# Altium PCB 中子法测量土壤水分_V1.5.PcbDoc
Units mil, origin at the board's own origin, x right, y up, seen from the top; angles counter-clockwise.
Board outline 3543.31 x 2393.7 mil, 4 copper layers (Top Layer, Signal Layer1, Signal Layer2, Bottom Layer), stack 30.634 mil thick; 164 components, 104 nets, 491 pads, 224 vias.
Unrouted connection lines stored in the file: 1.
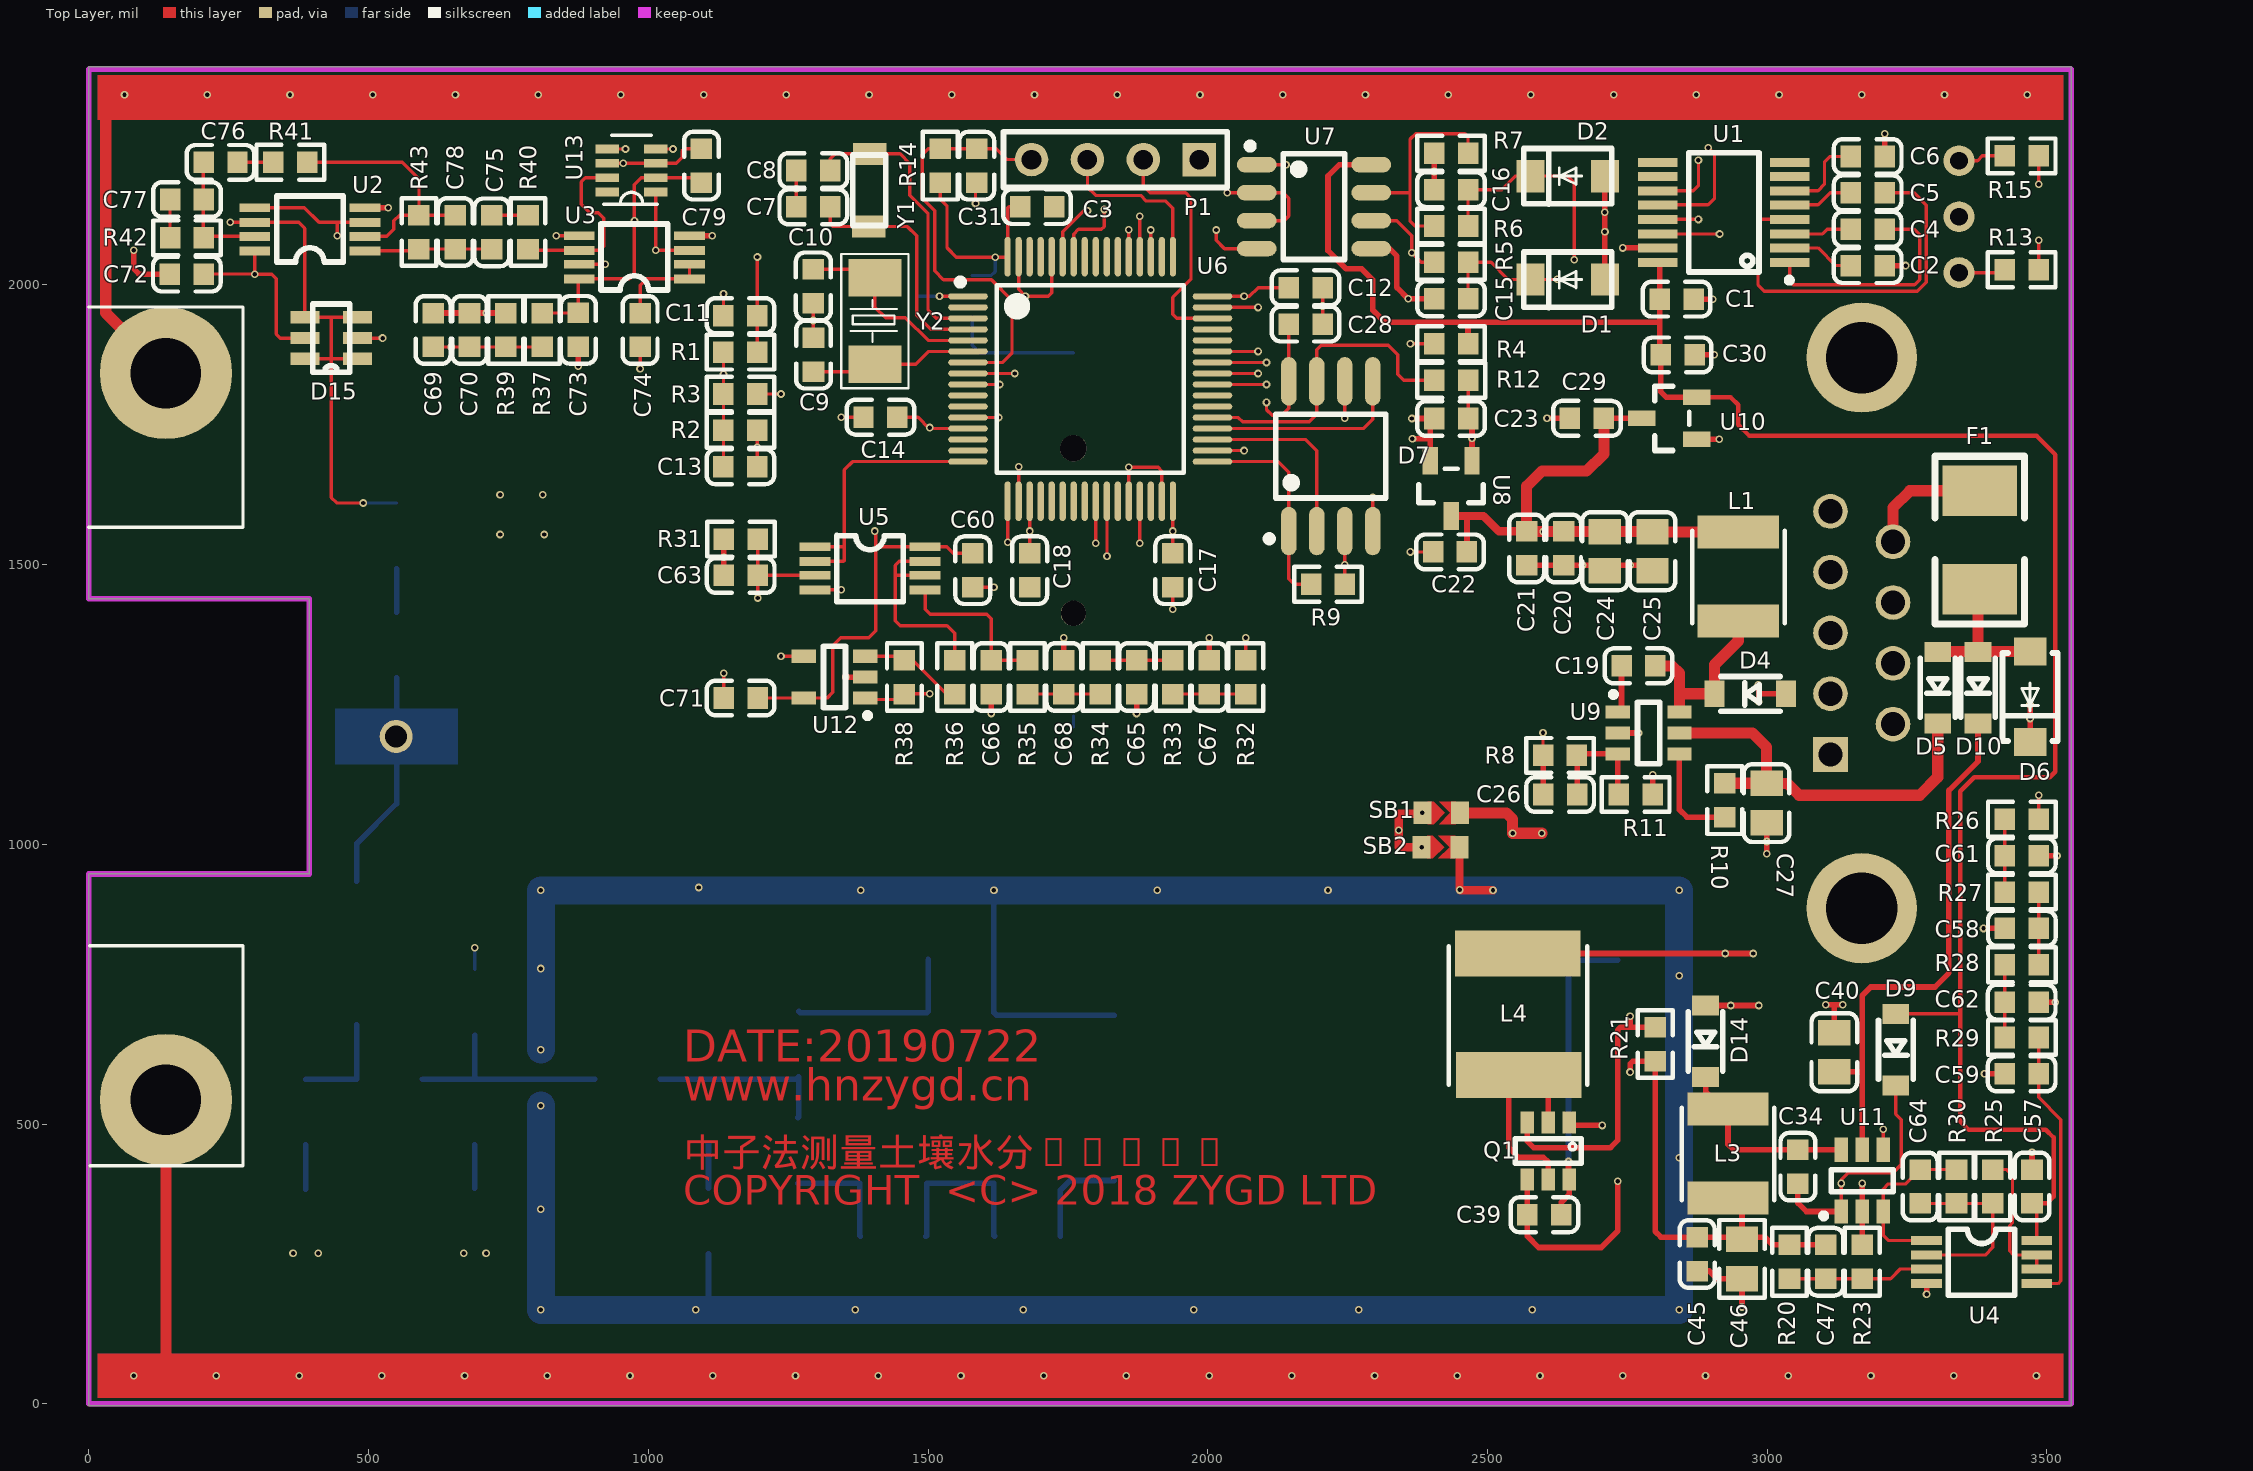
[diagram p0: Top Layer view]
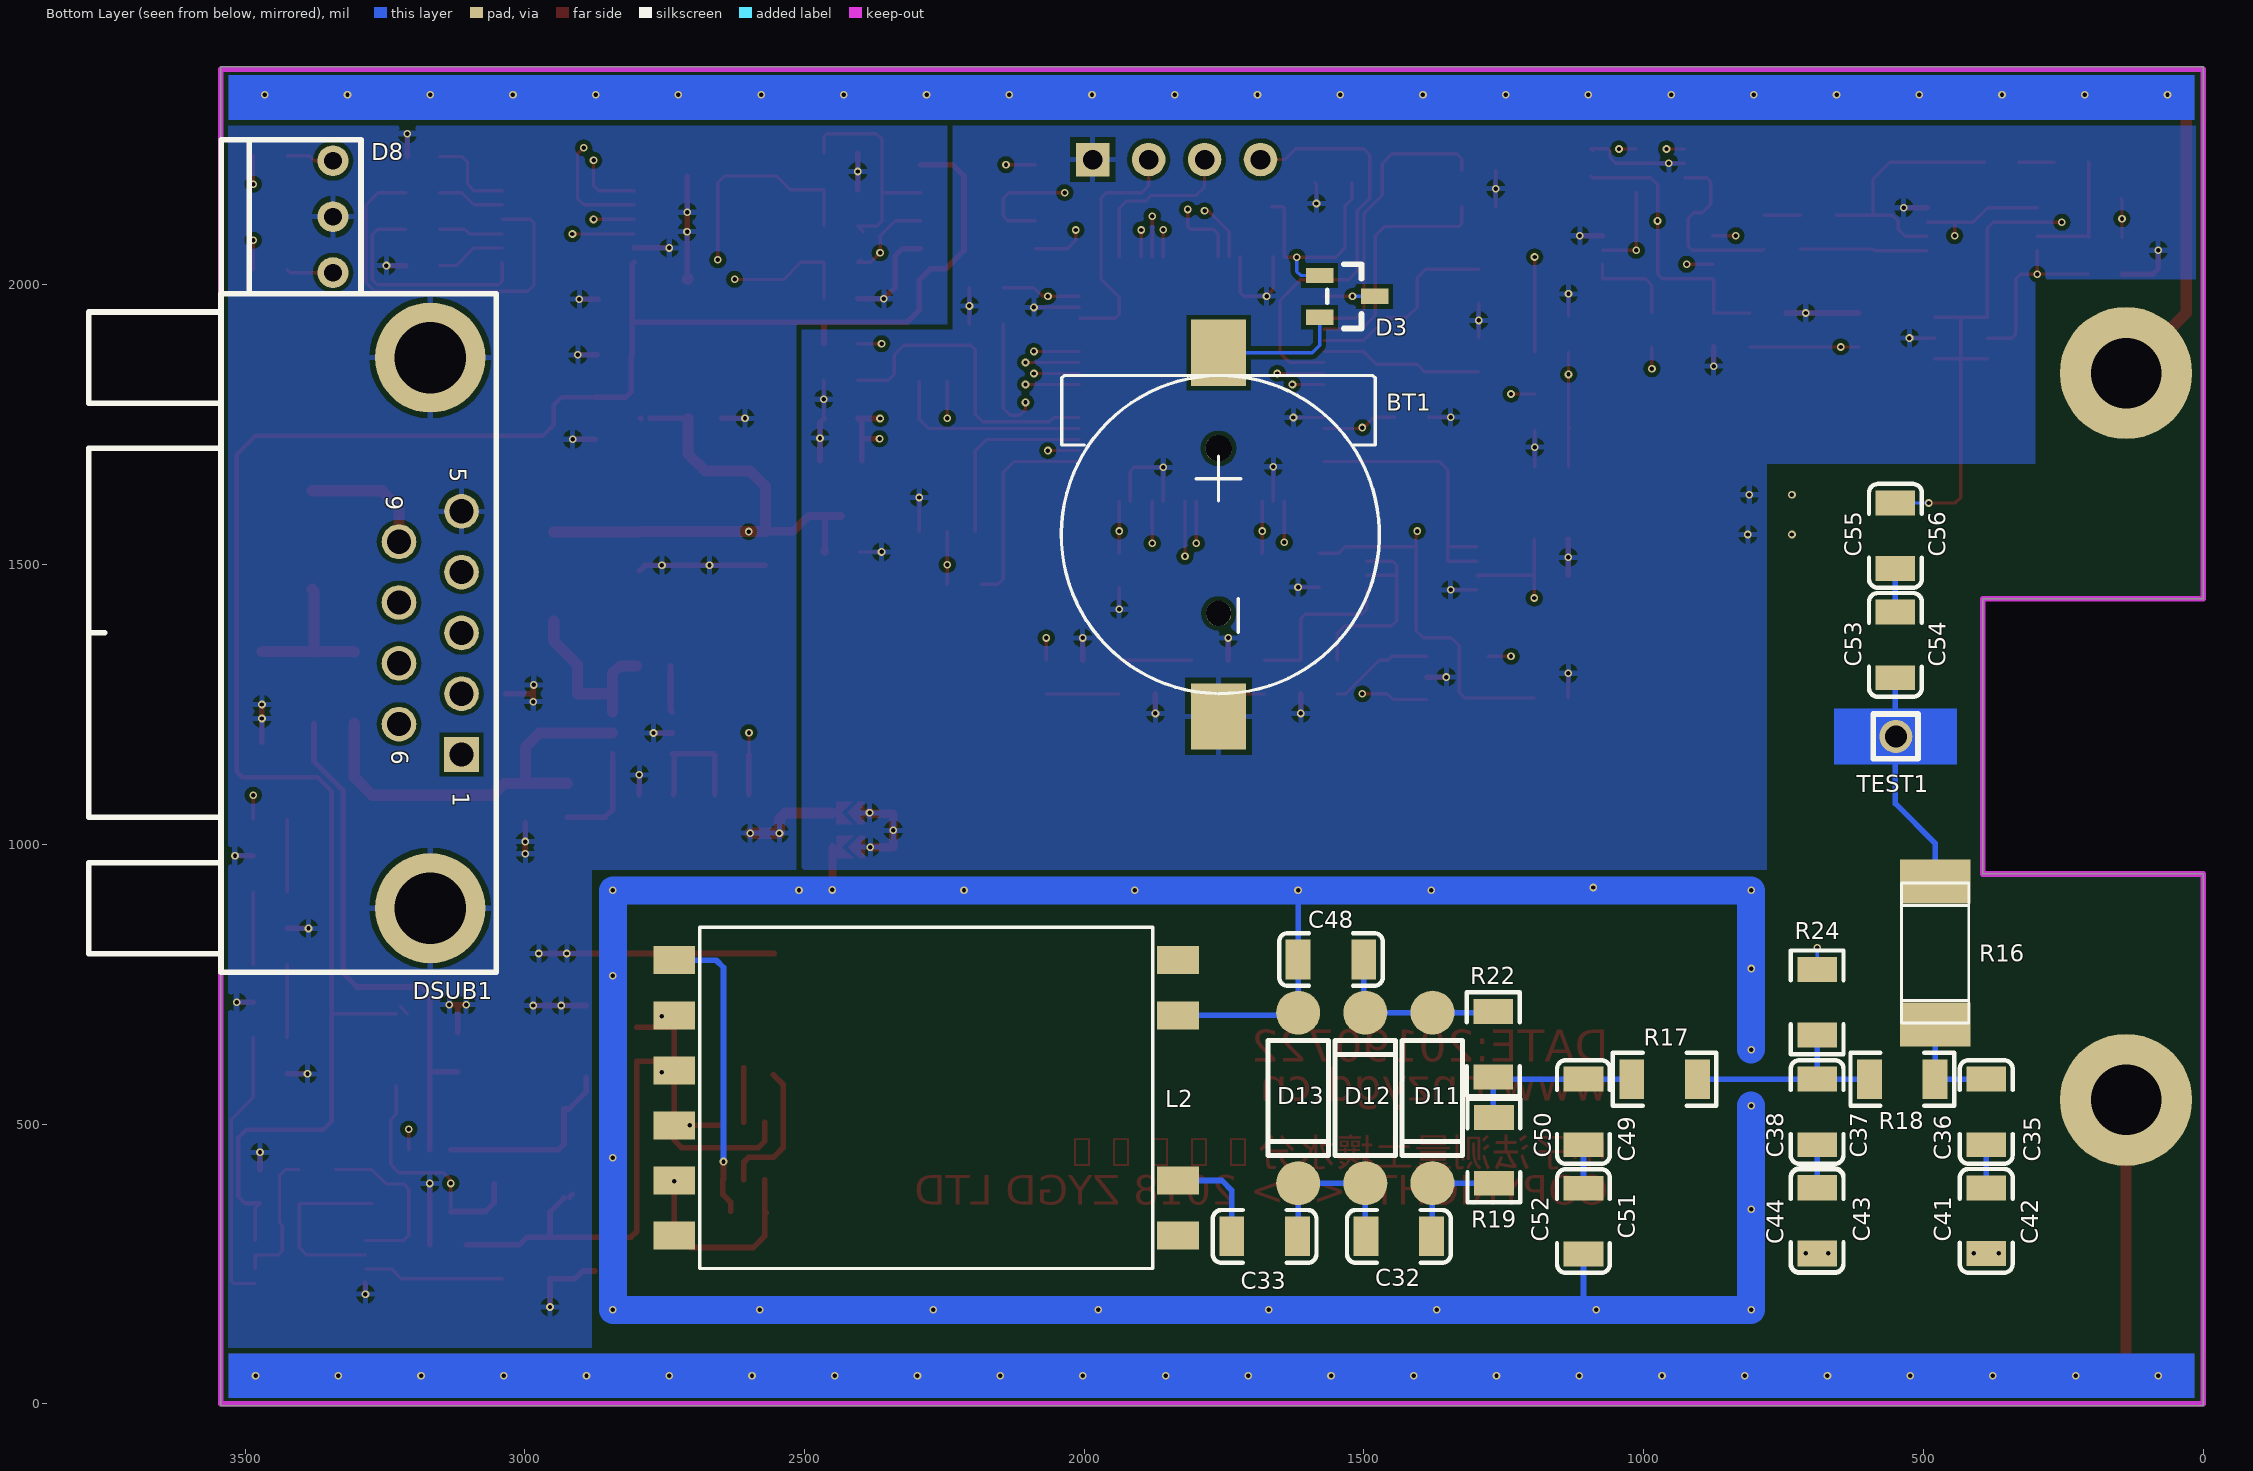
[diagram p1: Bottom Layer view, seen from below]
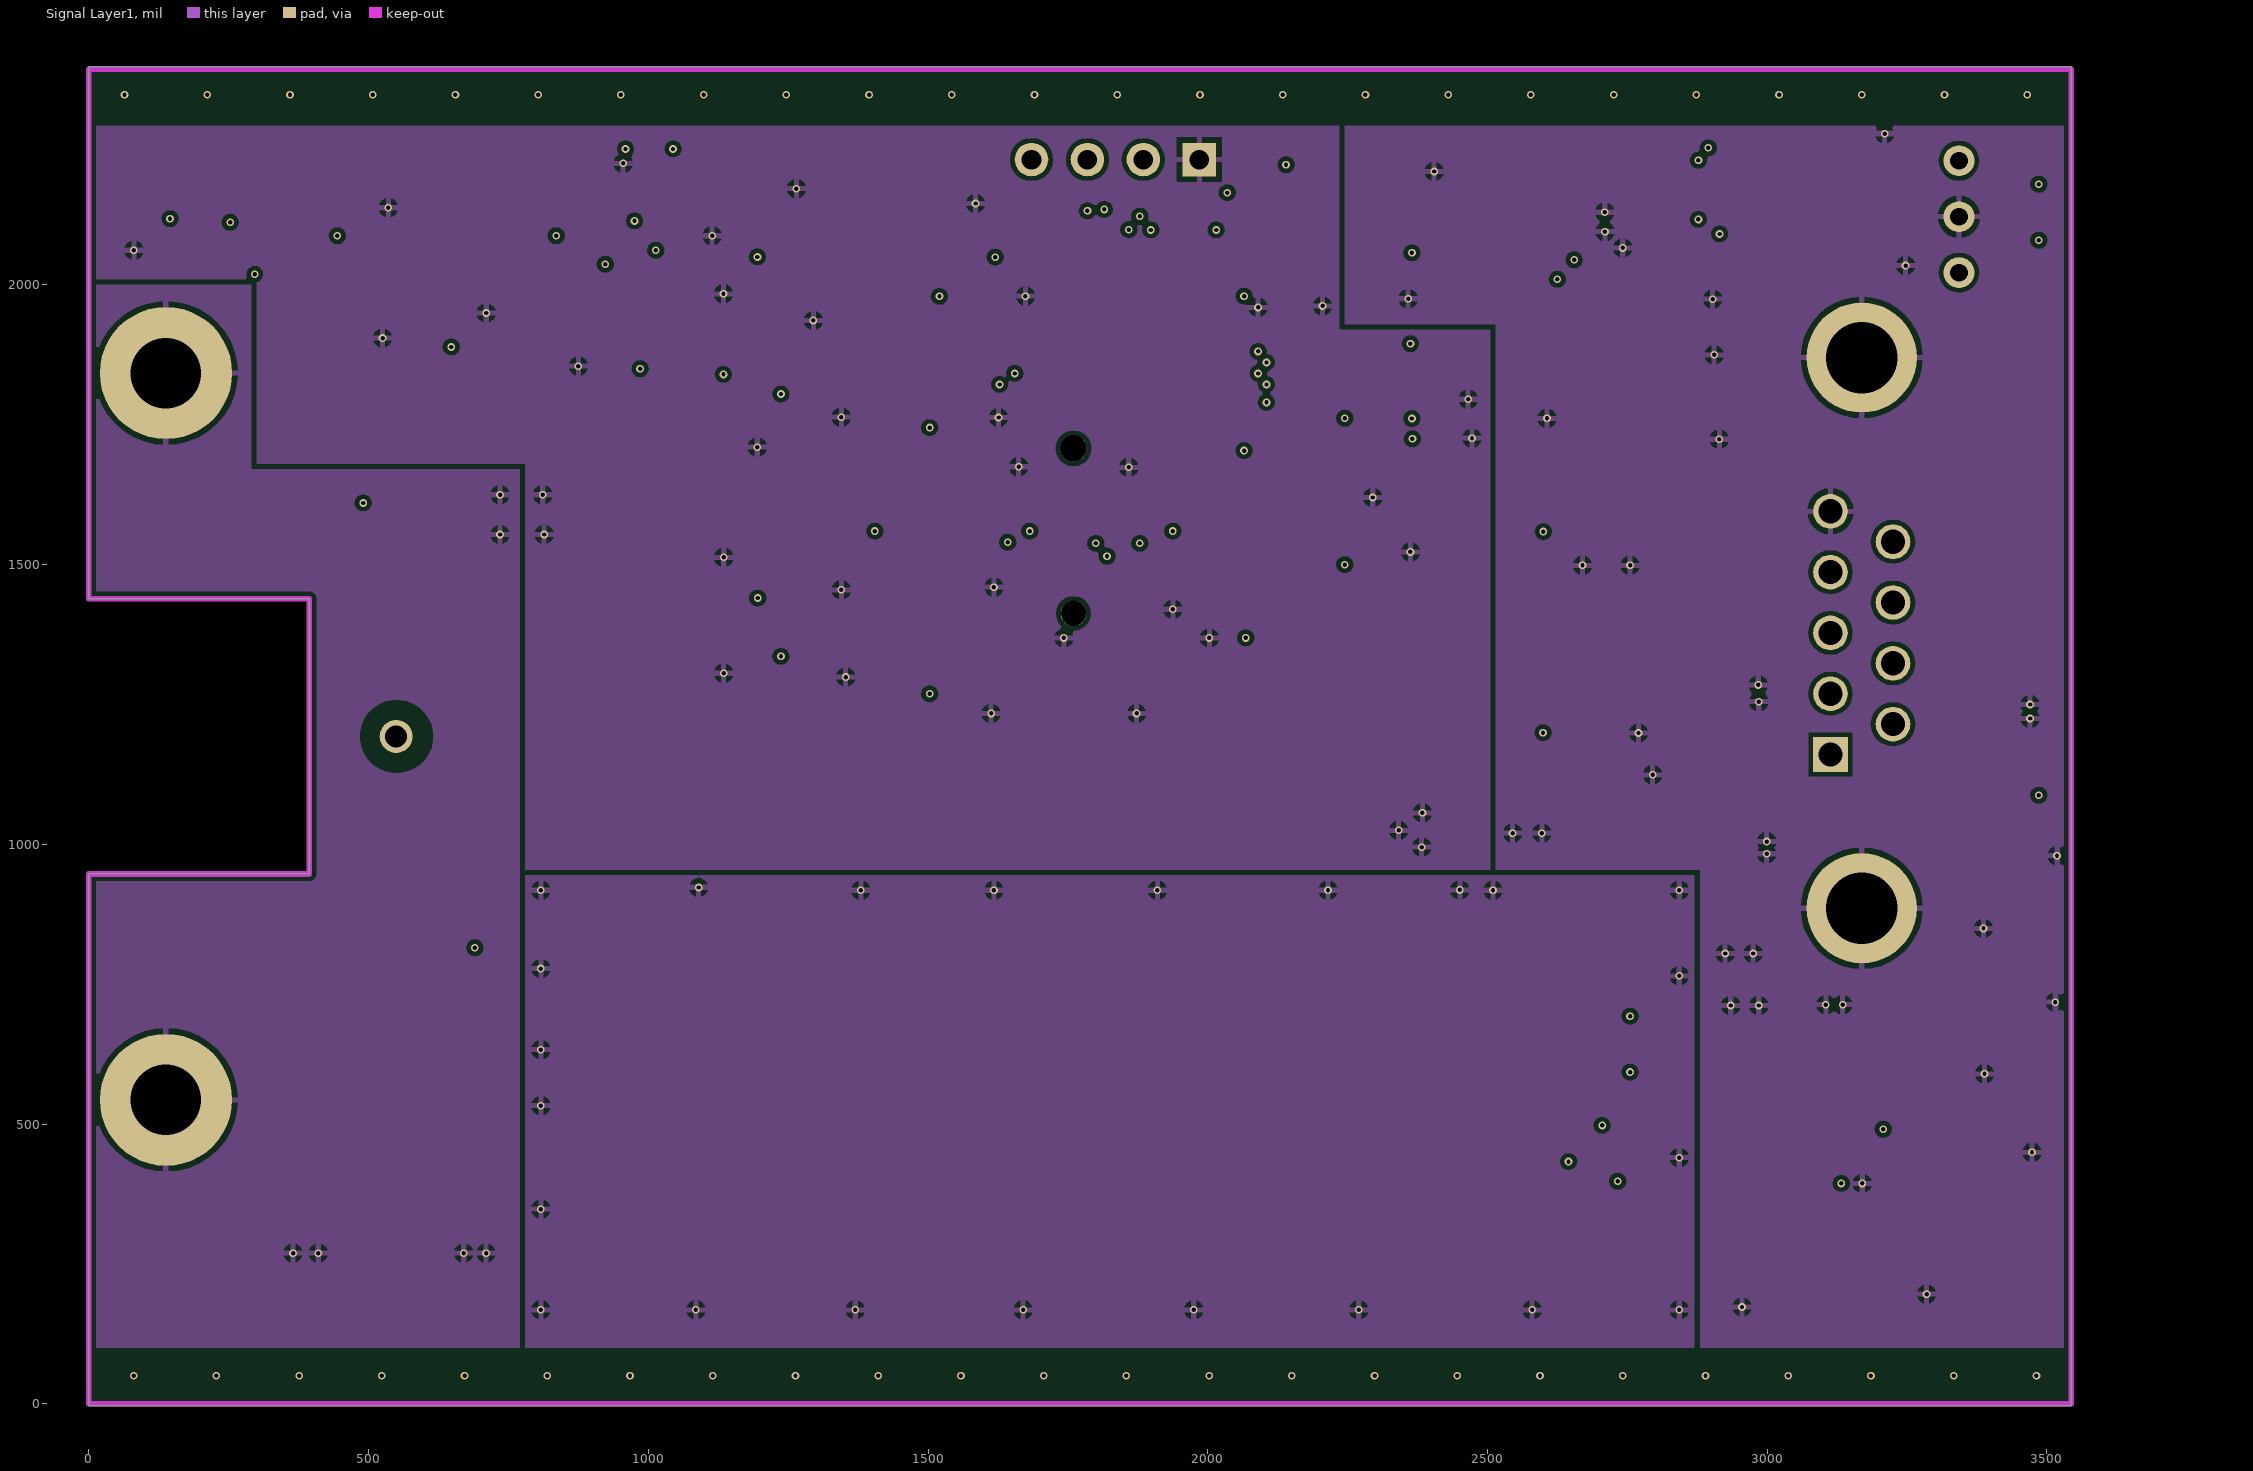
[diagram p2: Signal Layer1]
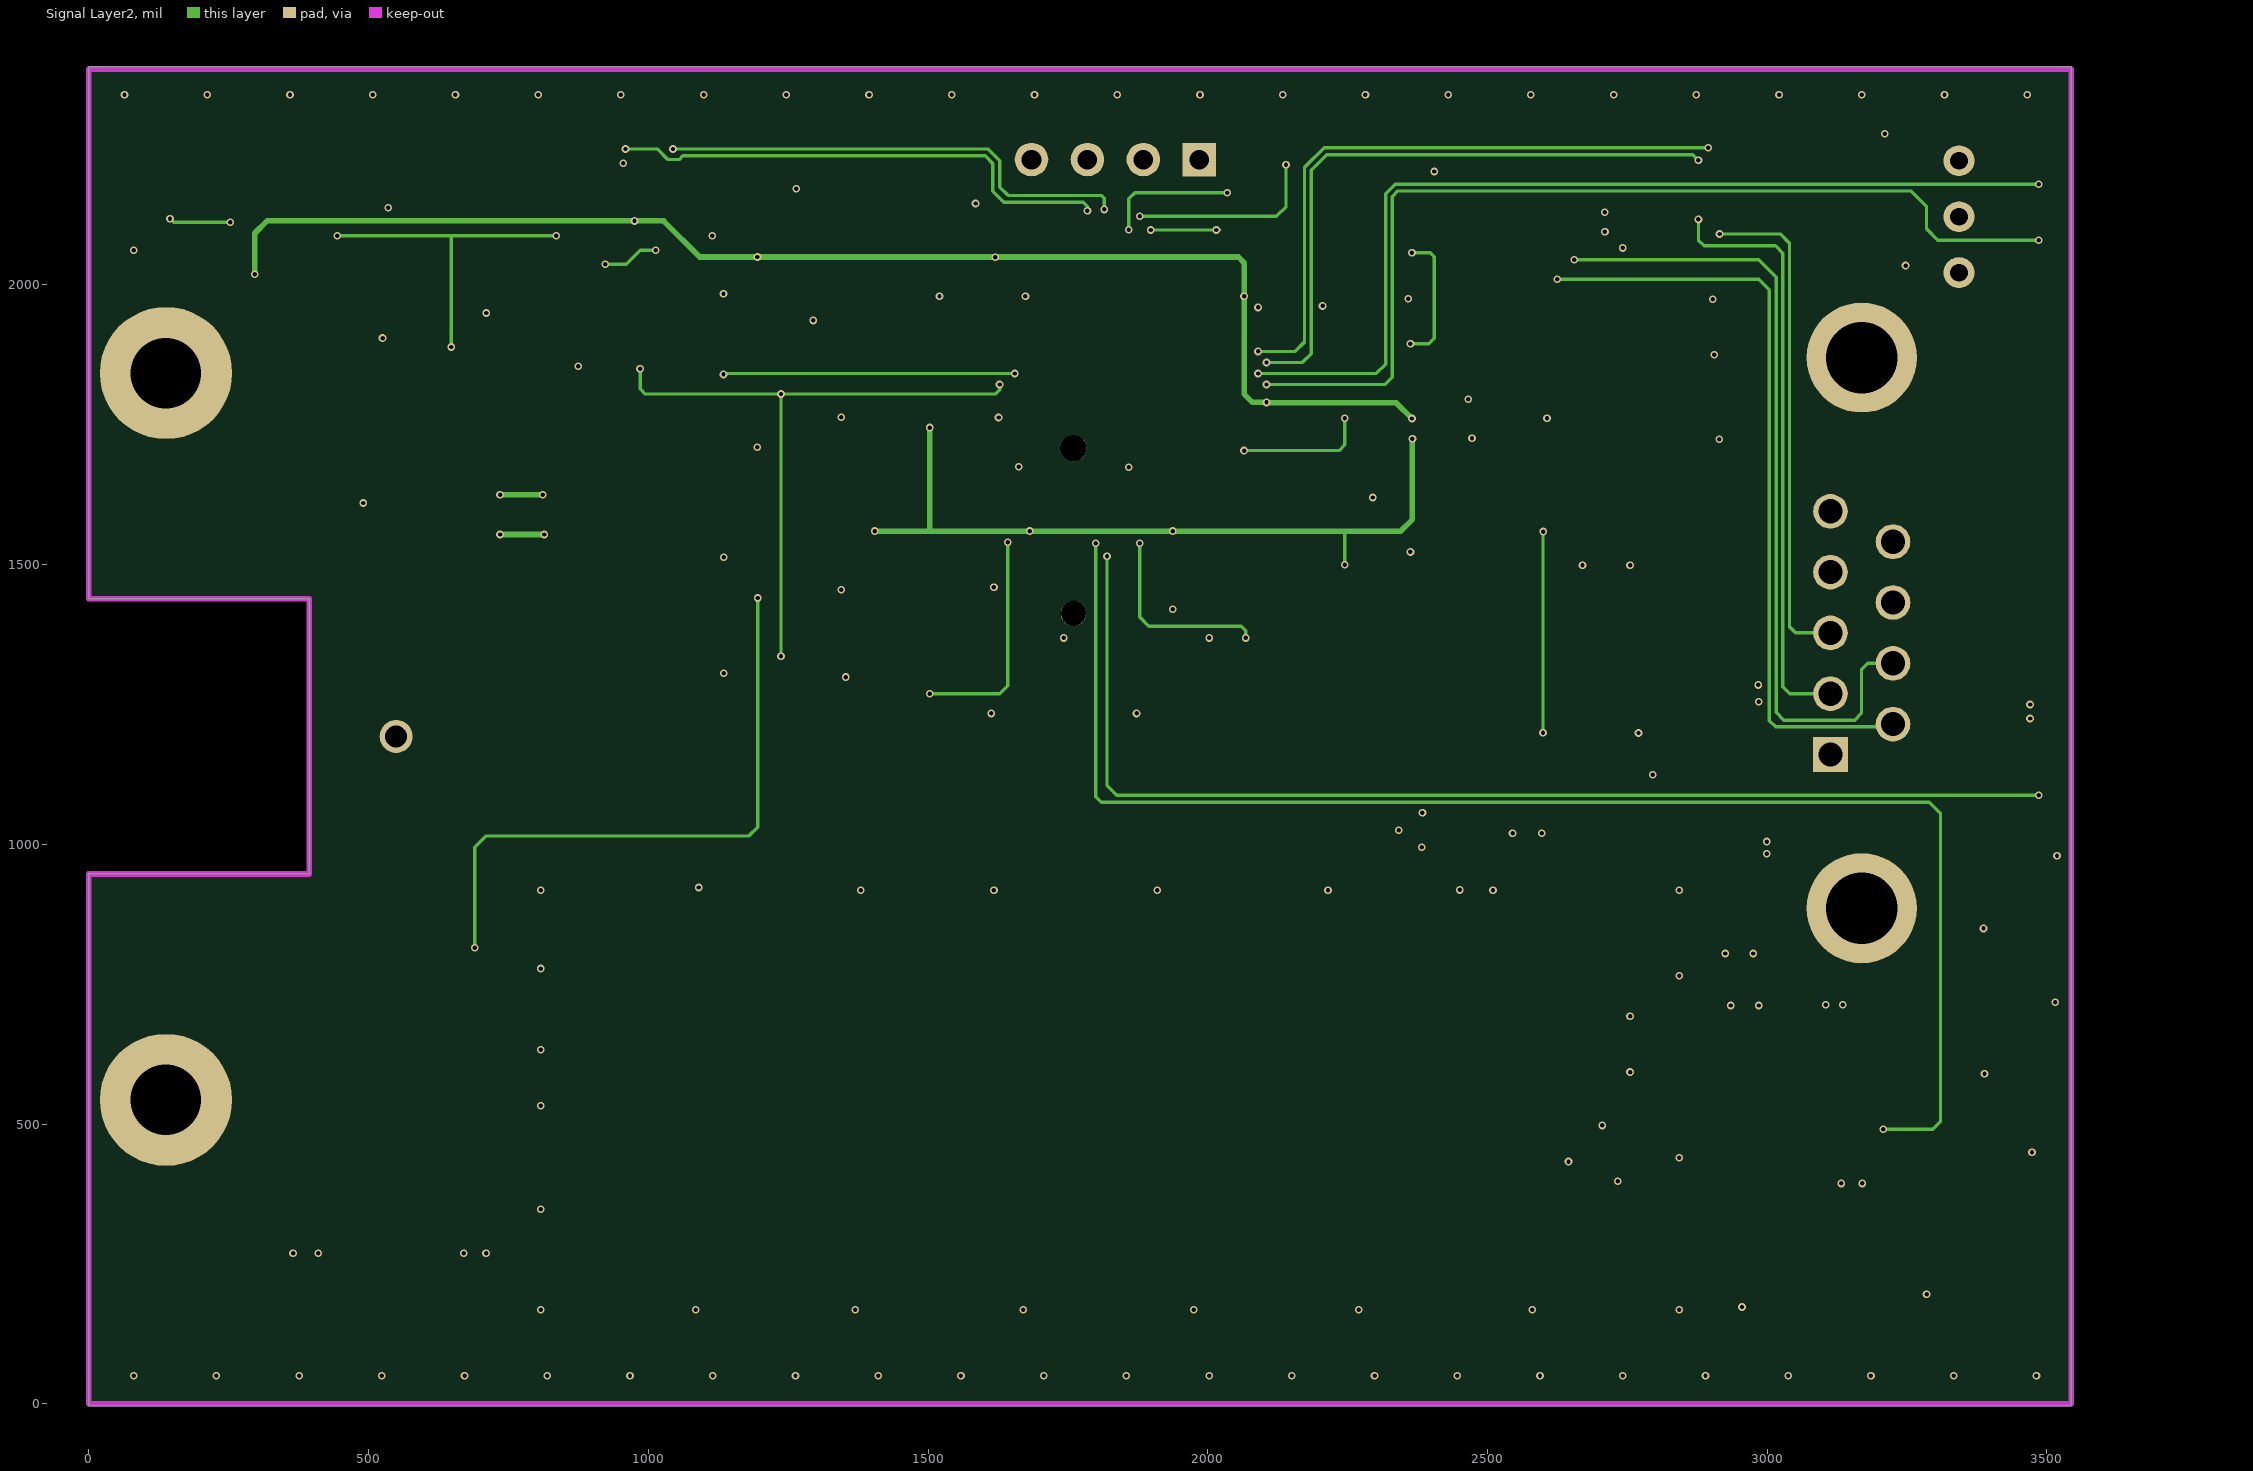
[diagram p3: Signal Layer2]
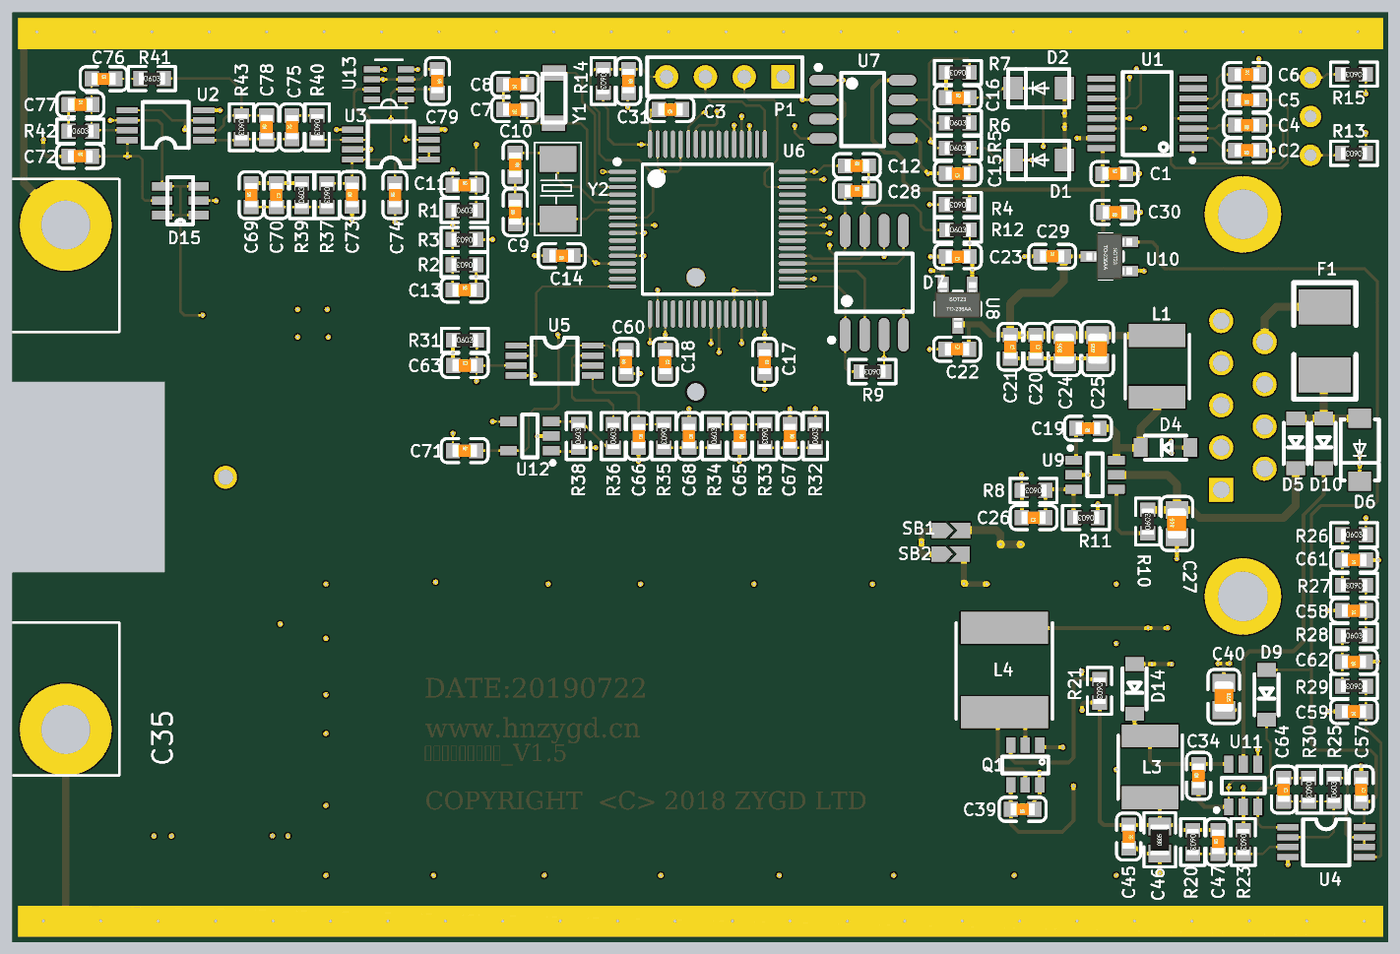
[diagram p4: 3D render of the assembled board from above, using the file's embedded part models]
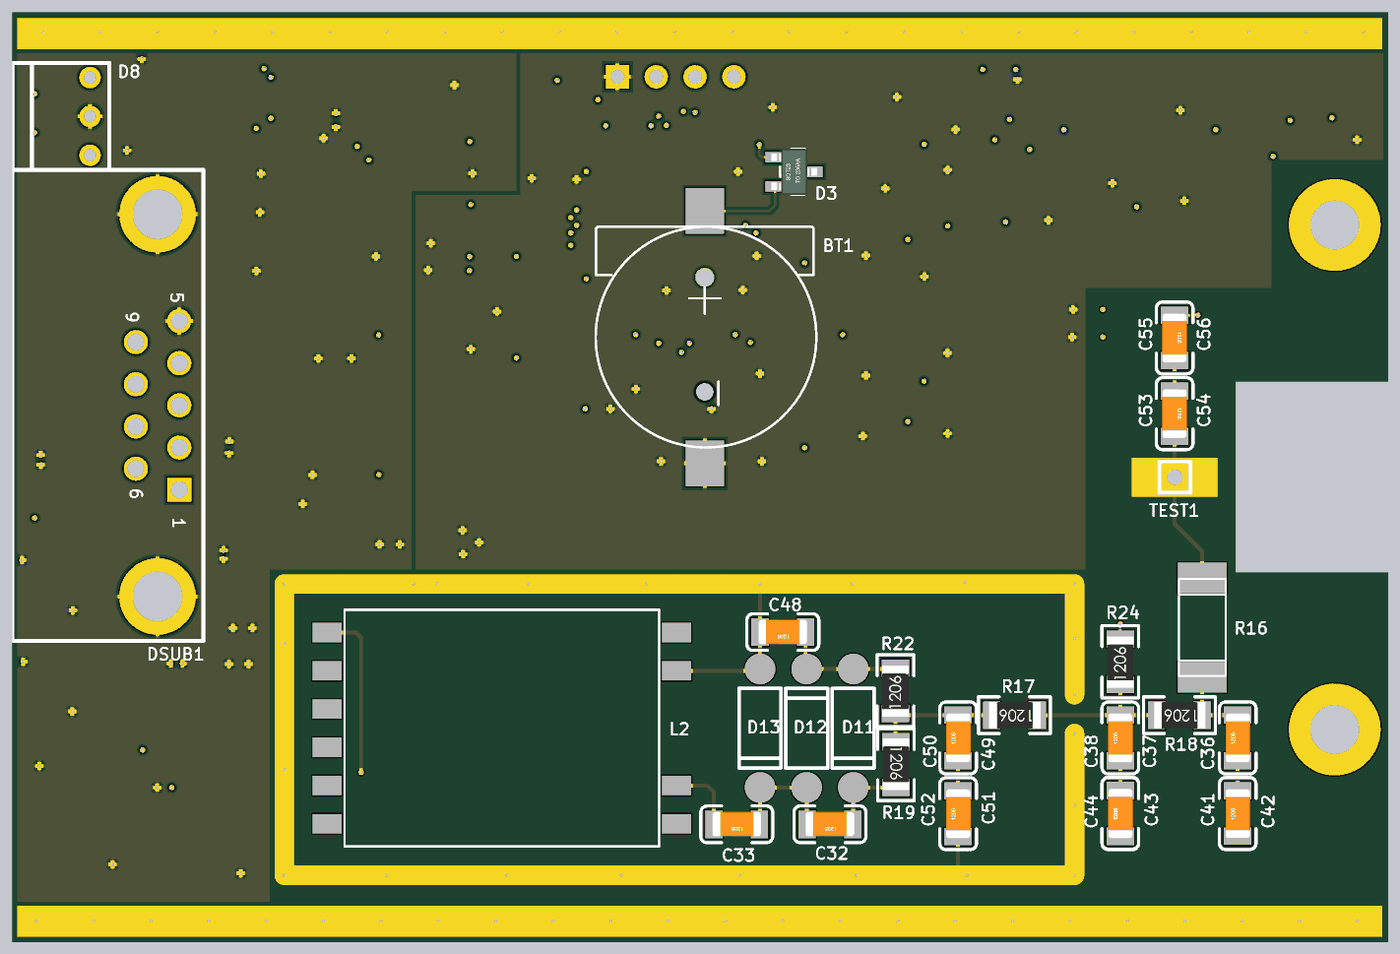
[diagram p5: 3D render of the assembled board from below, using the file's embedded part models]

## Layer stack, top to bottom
Top Solder: solder mask 0.4, Solder Resist, Dk 3.5
Top Layer: signal copper 1.4
Dielectric 1: core 10, FR-4, Dk 4.2
Signal Layer1: signal copper 1.417
Dielectric 3: prepreg 5, FR-4, Dk 4.2
Signal Layer2: signal copper 1.417
Dielectric 2: core 10, FR-4, Dk 4.2
Bottom Layer: signal copper 1.4
Bottom Solder: solder mask 0.4, Solder Resist, Dk 3.5

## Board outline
0,-3.94 0,947.01 393.7,947.01 393.7,1439.13 0,1439.13 0,2389.76 3543.31,2389.76 3543.31,-3.94

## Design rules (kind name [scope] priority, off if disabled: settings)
Clearance [All] p1: gap=6
MinimumSolderMaskSliver [All] p1: minsoldermaskwidth=6
PolygonConnect [All] p1: connectstyle=Relief reliefconductorwidth=10 reliefentries=4 polygonreliefangle="90 Angle" airgapwidth=10
RoomDefinition "Signal processing" [InComponentClass('Signal processing')] p1: confinementstyle=ConfineIn formatcopy=TRUE lockcomponents=FALSE outline -30120,-34112.09 -28120,-34112.09 -28120,-33112.09 -30120,-33112.09
RoomDefinition CPU_Circuit [InComponentClass('CPU_Circuit')] p2: confinementstyle=ConfineIn formatcopy=TRUE lockcomponents=FALSE outline -30120,-34112.09 -28120,-34112.09 -28120,-33112.09 -30120,-33112.09
RoutingVias [All] p1: holewidth=7.87 width=11.81 viastyle="Through Hole" minholewidth=7.87 minwidth=11.81 maxholewidth=39.37 maxwidth=50
SilkToSolderMaskClearance [IsPad] p1: minsilkscreentomaskgap=6 clearancetoexposedcopper=TRUE
SolderMaskExpansion [All] p1: expansion=4
Width [All] p1: maxlimit=50 minlimit=6 preferedwidth=10 minimp=50.000000 maximp=50.000000 favimp=50.000000
28 further rules are at their usual default settings.

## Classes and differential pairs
component class CPU_Circuit: BT1 C1 C2 C3 C4 C5 C6 C7 C8 C9 C10 C11 C12 C13 C14 C15 C16 C17 C18 C19 C20 C21 C22 C23 C24 C25 C26 C27 C28 C29 C30 C31 D1 D2 D3 D4 D5 D6 D7 D8 DSUB1 F1 L1 P1 R1 R2 R3 R4 R5 R6 R7 R8 R9 R10 R11 R12 R13 R14 R15 SB1 SB2 U1 U6 U7 U8 U9 U10 Y1 Y2
component class "Signal processing": C32 C33 C34 C35 C36 C37 C38 C39 C40 C41 C42 C43 C44 C45 C46 C47 C48 C49 C50 C51 C52 C53 C54 C55 C56 C57 C58 C59 C60 C61 C62 C63 C64 C65 C66 C67 C68 C69 C70 C71 C72 C73 C74 C75 C76 C77 C78 C79 D9 D10 D11 D12 D13 D14 D15 GND GND1 GND2 GND3 L2 L3 L4 Q1 R16 R17 R18 R19 R20 R21 R22 R23 R24 R25 R26 R27 R28 R29 R30 R31 R32 R33 R34 R35 R36 R37 R38 R39 R40 R41 R42 R43 TEST1 TEST4 U2 U3 U4 U5 U11 U12 U13

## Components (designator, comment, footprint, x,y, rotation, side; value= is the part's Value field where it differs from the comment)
BT1 "CR1220-2" BATTERY-2 1760,1553.82 r90 bottom
C1 "100nF(104) ±10% 50V" 0603_C 2838.16,1974.63 r0 top
C2 "100nF(104) ±10% 50V" 0603_C 3179.69,2034.63 r180 top
C3 "100nF(104) ±10% 50V" 0603_C 1695,2140 r180 top
C4 "100nF(104) ±10% 50V" 0603_C 3179.69,2099.63 r180 top
C5 "100nF(104) ±10% 50V" 0603_C 3179.69,2164.63 r180 top
C6 "100nF(104) ±10% 50V" 0603_C 3179.68,2229.63 r0 top
C7 "12PF (120) ±5% 50V" 0603_C 1295,2139.63 r180 top
C8 "12PF (120) ±5% 50V" 0603_C 1295,2204.63 r180 top
C9 "20PF (200) ±5% 50V" 0603_C 1295.33,1875.31 r90 top
C10 "20PF (200) ±5% 50V" 0603_C 1295.02,1997.49 r270 top
C11 "10nF(103) ±10% 50V" 0603_C 1164.69,1945 r0 top
C12 "100nF(104) ±10% 50V" 0603_C 2175,1995 r0 top
C13 "1uF(105) ±10% 50V" 0603_C 1164.69,1675 r0 top
C14 "100nF(104) ±10% 50V" 0603_C 1415,1763.64 r180 top
C15 "10nF(103) ±10% 50V" 0603_C 2435,1975.33 r180 top
C16 "10nF(103) ±10% 50V" 0603_C 2435,2170.33 r0 top
C17 "100nF(104) ±10% 50V" 0603_C 1937.64,1490 r270 top
C18 "100nF(104) ±10% 50V" 0603_C 1681.73,1490 r270 top
C19 "100nF(104) ±10% 50V" 0603_C 2770,1319.09 r180 top
C20 "100nF(104) ±10% 50V" 0603_C 2636.17,1529.05 r270 top
C21 "100nF(104) ±10% 50V" 0603_C 2570,1529.05 r270 top
C22 "1uF(105) ±10% 50V" 0603_C 2433.1,1522.7 r0 top
C23 "1uF(105) ±10% 50V" 0603_C 2435,1761.17 r180 top
C24 "10uF(106) ±10% 25V" 0805_C 2710,1524.05 r90 top
C25 "10uF(106) ±10% 25V" 0805_C 2795,1524.05 r90 top
C26 "33pF(330) ±5% 50V" 0603_C 2630,1089.09 r180 top
C27 "10uF(106) ±10% 25V" 0805_C 2999.09,1073.85 r90 top
C28 "100nF(104) ±10% 50V" 0603_C 2175,1930 r0 top
C29 "1uF(105) ±10% 50V" 0603_C 2677.84,1761.52 r0 top
C30 "1uF(105) ±10% 50V" 0603_C 2840,1875 r180 top
C31 "100nF(104) ±10% 50V" 0603_C 1587.07,2213.16 r270 top
C32 "4.7nF(472) ±10% 2KV" 1206_C 1437.65,299.17 r0 bottom
C33 "4.7nF(472) ±10% 2KV" 1206_C 1677.65,299.17 r0 bottom
C34 "100nF(104) ±10% 50V" 0603_C 3055,423.87 r90 top
C35 "4.7nF(472) ±10% 2KV" 1206_C 387.66,521.57 r90 bottom
C36 "4.7nF(472) ±10% 2KV" 1206_C 387.66,521.57 r90 bottom
C37 "4.7nF(472) ±10% 2KV" 1206_C 690,521.57 r90 bottom
C38 "4.7nF(472) ±10% 2KV" 1206_C 690,521.57 r90 bottom
C39 "220nF (224) ±10% 25V" 0603_C 2601.8,337.87 r180 top
C40 "10uF(106) ±10% 25V" 0805_C 3120.04,628.37 r270 top
C41 "4.7nF(472) ±10% 2KV" 1206_C 387.66,326.98 r90 bottom
C42 "4.7nF(472) ±10% 2KV" 1206_C 387.66,326.98 r90 bottom
C43 "4.7nF(472) ±10% 2KV" 1206_C 690,326.57 r90 bottom
C44 "4.7nF(472) ±10% 2KV" 1206_C 690,327.95 r90 bottom
C45 "100nF(104) ±10% 50V" 0603_C 2875,267.6 r270 top
C46 "22uF(226) ±20% 25V" 0805_R 2955,258.87 r90 top
C47 "33pF(330) ±5% 50V" 0603_C 3104.96,253.87 r90 top
C48 "4.7nF(472) ±10% 2KV" 1206_C 1558.98,794.17 r0 bottom
C49 "4.7nF(472) ±10% 2KV" 1206_C 1107.66,521.57 r90 bottom
C50 "4.7nF(472) ±10% 2KV" 1206_C 1107.66,521.57 r90 bottom
C51 "4.7nF(472) ±10% 2KV" 1206_C 1107.66,326.57 r90 bottom
C52 "4.7nF(472) ±10% 2KV" 1206_C 1107.66,326.57 r90 bottom
C53 "100pF(101) ±5% 2kV" 1206_C 550,1356.57 r270 bottom
C54 "100pF(101) ±5% 2kV" 1206_C 550,1356.57 r270 bottom
C55 "100pF(101) ±5% 2kV" 1206_C 550,1551.57 r270 bottom
C56 "100pF(101) ±5% 2kV" 1206_C 550,1551.57 r270 bottom
C57 "10nF(103) ±10% 50V" 0603_C 3473.5,388.39 r270 top
C58 "100nF(104) ±10% 50V" 0603_C 3455.32,849.73 r180 top
C59 "10nF(103) ±10% 50V" 0603_C 3455,589.73 r180 top
C60 "10nF(103) ±10% 50V" 0603_C 1580,1490 r90 top
C61 "220nF (224) ±10% 25V" 0603_C 3455.32,979.73 r180 top
C62 "47nF(473) ±10% 50V" 0603_C 3455,717.91 r180 top
C63 "1nF(102) ±10% 50V" 0603_C 1165.22,1480.68 r0 top
C64 "1nF(102) ±10% 50V" 0603_C 3273.5,388.39 r270 top
C65 "100nF(104) ±10% 50V" 0603_C 1872.84,1299.02 r270 top
C66 "10nF(103) ±10% 50V" 0603_C 1612.84,1299.02 r270 top
C67 "220nF (224) ±10% 25V" 0603_C 2002.84,1299.02 r270 top
C68 "47nF(473) ±10% 50V" 0603_C 1742.84,1299.02 r270 top
C69 "1nF(102) ±10% 50V" 0603_C 615.31,1919.45 r90 top
C70 "1uF(105) ±10% 50V" 0603_C 680.31,1919.45 r270 top
C71 "10nF(103) ±10% 50V" 0603_C 1165,1261.62 r0 top
C72 "10nF(103) ±10% 50V" 0603_C 175,2019.45 r0 top
C73 "10nF(103) ±10% 50V" 0603_C 875,1919.76 r90 top
C74 "1uF(105) ±10% 50V" 0603_C 985.31,1919.45 r90 top
C75 "100nF(104) ±10% 50V" 0603_C 720.31,2094.13 r90 top
C76 "100nF(104) ±10% 50V" 0603_C 235.31,2219.13 r0 top
C77 "1pF(010) ±0.25pF 50V" 0603_C 175.32,2152.75 r0 top
C78 "1nF(102) ±10% 50V" 0603_C 655,2094.45 r90 top
C79 "10nF(103) ±10% 50V" 0603_C 1095,2213.16 r270 top
D1 "SMAJ10CA" SMA/DO-214AC 2643.5,2009.63 r180 top
D2 "SMAJ10CA" SMA/DO-214AC 2643.5,2194.63 r180 top
D3 "BAT54C" SOT-23(SOT-23-3) 1530,1979.54 r0 bottom
D4 "B5819W" SOD-123 2970,1269.09 r0 top
D5 "B5819W" SOD-123 3305,1280 r90 top
D6 "SMAJ20CA" SMA(DO-214AC) 3470,1263.7 r270 top
D7 "W25Q128FVSIG" SOIC-8_208mil 2220,1693.86 r90 top
D8 "L-130WDT_1EGW" L-130WDT_1EGW 3343,2122.05 r270 bottom
D9 "B5819W" SOD-123 3230,632.91 r90 top
D10 "B5819W" SOD-123 3377,1280 r90 top
D11 "R3000F" R3000F 1377.65,546.67 r270 bottom
D12 "R3000F" R3000F 1497.65,546.67 r90 bottom
D13 "R3000F" R3000F 1617.65,546.67 r270 bottom
D14 "B5819W" SOD-123 2890,647.91 r90 top
D15 "PRTR5V0U4D" TSOP-6 433,1905 r180 top
DSUB1 "DMR-9S" DMR-9S 3169.1,1377.95 r0 bottom
F1 "mSMD050-60V" 1812 3380,1544 r270 top
L1 "4.7uH ±20% 1.34A" IND-404020 2948.34,1478.59 r270 top
L2 "FL2015-5L" FL2015-5L 1832.65,792.87 r0 bottom
L3 "4.7uH ±20% 1.34A" IND-404020 2930.04,447.37 r270 top
L4 "1mH ±20% 0.3A" IND-606045 2555.09,696.41 r90 top
P1 "4P-2.54排针" 4P排针 1985,2224.13 r180 top
Q1 "FMB2222A" SUPERSOT-6(SSOT-6) 2608.77,451.77 r180 top
R1 "7.5KΩ(7501) ±1%" 0603_R 1164.69,1880 r0 top
R2 "7.5KΩ(7501) ±1%" 0603_R 1164.69,1740 r180 top
R3 "1KΩ(1001) ±1%" 0603_R 1164.69,1805 r180 top
R4 "10KΩ(1002) ±1%" 0603_R 2435,1895 r180 top
R5 "100Ω (1000) ±1%" 0603_R 2435,2040.33 r0 top
R6 "100Ω (1000) ±1%" 0603_R 2435,2105.33 r0 top
R7 "10KΩ(1002) ±1%" 0603_R 2435,2235.33 r180 top
R8 "82KΩ (8202) ±1%" 0603_R 2629.69,1159.09 r180 top
R9 "10KΩ(1002) ±1%" 0603_R 2215,1465 r180 top
R10 "100KΩ(1003) ±1%" 0603_R 2924.09,1078.85 r90 top
R11 "20KΩ(2002) ±1%" 0603_R 2765,1089.09 r180 top
R12 "10KΩ(1002) ±1%" 0603_R 2435.31,1829.67 r0 top
R13 "1KΩ(1001) ±1%" 0603_R 3455,2027.02 r180 top
R14 "10KΩ(1002) ±1%" 0603_R 1521.76,2213.16 r270 top
R15 "1KΩ(1001) ±1%" 0603_R 3455,2230.72 r180 top
R16 "10MΩ(106) ±5%" 2512 479,805.87 r270 bottom
R17 "1MΩ(1004) ±1%" 1206_R 962.66,580.24 r0 bottom
R18 "1MΩ(1004) ±1%" 1206_R 537.66,580.24 r0 bottom
R19 "1MΩ(1004) ±1%" 1206_R 1267.66,452.87 r270 bottom
R20 "20KΩ(2002) ±1%" 0603_R 3039.96,253.87 r270 top
R21 "2KΩ(2001) ±1%" 0603_R 2800,642.91 r270 top
R22 "1MΩ(1004) ±1%" 1206_R 1268.98,642.87 r90 bottom
R23 "20KΩ(2002) ±1%" 0603_R 3169.96,253.87 r270 top
R24 "100MΩ(1006) ±1%" 1206_R 690,717.54 r90 bottom
R25 "10KΩ(1002) ±1%" 0603_R 3403.5,388.39 r90 top
R26 "100KΩ(1003) ±1%" 0603_R 3455.32,1044.73 r0 top
R27 "100KΩ(1003) ±1%" 0603_R 3455.32,914.73 r180 top
R28 "100KΩ(1003) ±1%" 0603_R 3455.32,784.73 r0 top
R29 "100KΩ(1003) ±1%" 0603_R 3455.32,654.73 r180 top
R30 "20KΩ(2002) ±1%" 0603_R 3338.5,388.39 r270 top
R31 "100KΩ(1003) ±1%" 0603_R 1165.54,1545.68 r0 top
R32 "100KΩ(1003) ±1%" 0603_R 2067.84,1299.02 r90 top
R33 "100KΩ(1003) ±1%" 0603_R 1937.84,1299.02 r270 top
R34 "100KΩ(1003) ±1%" 0603_R 1807.84,1299.02 r90 top
R35 "100KΩ(1003) ±1%" 0603_R 1677.84,1299.02 r270 top
R36 "1KΩ(1001) ±1%" 0603_R 1547.84,1299.02 r90 top
R37 "10KΩ(1002) ±1%" 0603_R 810.31,1919.45 r270 top
R38 "100KΩ(1003) ±1%" 0603_R 1457.84,1299.02 r90 top
R39 "10KΩ(1002) ±1%" 0603_R 745.31,1919.45 r90 top
R40 "499Ω(4990) ±1%" 0603_R 785,2094.45 r270 top
R41 "1KΩ(1001) ±1%" 0603_R 360,2219.45 r0 top
R42 "22MΩ(226) ±5%" 0603_R 175.31,2084.13 r0 top
R43 "20KΩ(2002) ±1%" 0603_R 590,2094.45 r270 top
SB1 "SB" SB_0603 2417.5,1056.25 r180 top
SB2 "SB" SB_0603 2416.25,995 r180 top
TEST1 "TEST" TEST 549.27,1192.91 r270 bottom
U1 "SP3232EEY-L/TR" TSSOP-16 2922.53,2129.63 r180 top
U2 "RS8752XM" MSOP-8 395,2099.45 r180 top
U3 "RS8752XM" MSOP-8 975,2049.45 r180 top
U4 "RS8752XM" MSOP-8 3383.5,253.39 r0 top
U5 "RS8752XM" MSOP-8 1396.34,1493.5 r0 top
U6 "STM32F103RET6" LQFP-64_10x10x05P 1790,1831.9 r270 top
U7 "SP3485EN-L/TR" SOIC-8_150mil 2190,2140 r270 top
U8 "MCP1700T-3302E/TT" SOT-23(SOT-23-3) 2435,1636.17 r90 top
U9 "MP2451DT-LF-Z" SOT-23-6 2788.03,1199.09 r180 top
U10 "MCP1700T-3302E/TT" SOT-23(SOT-23-3) 2825,1761.52 r0 top
U11 "MP2451DT-LF-Z" SOT-23-6 3170,398.87 r270 top
U12 "TP1961-TR" SOT-23-5 1332.84,1299.02 r0 top
U13 "AD5245BRJZ10-RL7" SOT-23-8 970,2204.45 r180 top
Y1 "32.768KHz ±20ppm 12.5pF" SMD-3215_2P 1395,2169.32 r270 top
Y2 "SX530GA 8MHZ 20PF 10PPM" SMD-5032_2P 1405.02,1935.31 r90 top

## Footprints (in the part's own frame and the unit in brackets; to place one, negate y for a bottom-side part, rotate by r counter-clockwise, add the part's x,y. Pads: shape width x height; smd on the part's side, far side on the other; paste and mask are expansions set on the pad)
4P排针 [mil] "2.54排针"
  rect 60x60 hole 35: 1(0,0)
  round 60 hole 35: 2(100,0) 3(200,0) 4(300,0)
  silkscreen extent -50,-50 350,50
0603_C [mm]
  rect 0.93x0.98 smd: 1(-0.77,0) 2(0.77,0)
  silkscreen extent -1.53,-0.79 1.54,0.79, body extent -0.8,-0.4 0.8,0.4, height 0.3
0603_R [mm]
  rect 0.93x0.98 smd: 1(-0.77,0) 2(0.77,0)
  silkscreen extent -1.53,-0.79 1.54,0.79, body extent -0.85,-0.4 0.85,0.4, height 0.56
0805_C [mm]
  rect 1.16x1.47 smd: 1(-0.89,0) 2(0.89,0)
  silkscreen extent -1.77,-1.04 1.77,1.04, body extent -1,-0.62 1,0.63, height 0.77
0805_R [mm]
  rect 1.16x1.47 smd: 1(-0.89,0) 2(0.89,0)
  silkscreen extent -1.77,-1.04 1.77,1.03, body extent -1,-0.62 1,0.63, height 0.49
1206_C [mm]
  rect 1.13x1.8 smd: 1(-1.49,0) 2(1.49,0)
  silkscreen extent -2.36,-1.2 2.35,1.2, body extent -1.6,-0.81 1.6,0.79, height 1
1206_R [mm]
  rect 1.13x1.8 smd: 1(-1.49,0) 2(1.49,0)
  silkscreen extent -2.36,-1.2 2.35,1.2, body extent -1.7,-0.86 1.65,0.87, height 0.85
1812 [mil]
  rect 90x133.86 smd: 1(-88,0) 2(88,0)
  silkscreen extent -150,-80 150,80
2512 [mil]
  rect 78.7x126 smd: 1(-128,0) 2(128,0)
  silkscreen extent -125,-60 125,60
BATTERY-2 [mm]
  round 1.152 hole 1.152 unplated paste+1.152 mask+0.148: 0(-3.581,0)
  round 1.2 hole 1.2: 0(3.912,0)
  rect 3x2.5 smd: 1(8.255,0) 2(-8.255,0)
  silkscreen extent -7.22,-7.3 7.22,7.14
DMR-9S [mil]
  rect 62x62 hole 43.31: 1(-55.9,217.32)
  round 62 hole 43.31: 2(-55.9,108.65) 3(-55.9,0) 4(-55.9,-108.67) 5(-55.9,-217.32) 6(55.9,162.99) 7(55.9,54.33) 8(55.9,-54.33) 9(55.9,-162.99)
  round 196.85 hole 127.95: 10(-0.01,492.12) 11(-0.01,-492.12)
  silkscreen extent -118,-606 610,606
FL2015-5L [mm] "CCFL升压变压器"
  rect 1.9x1.27 smd: 1(22.865,0) 2(22.865,2.5) 3(22.865,5) 4(22.865,7.5) 5(22.865,10) 6(22.865,12.5) 7(0,12.5) 8(0,10) 9(0,2.5) 10(0,0)
  silkscreen extent 1.14,-1.5 21.72,13.99
IND-404020 [mm]
  rect 1.5x3.7 smd: 1(2.019,0) 2(-2.019,0)
  silkscreen extent -2.08,-2.09 2.12,2.11
IND-606045 [mil]
  rect 82.68x224.41 smd: 1(108.5,0.5) 2(-108.5,-0.5)
  silkscreen extent -127,-124 122,125
L-130WDT_1EGW [mm] "红绿二合一LED"
  round 1.4 hole 0.8: 1(-2.54,0) 2(0,0) 3(2.54,0)
  silkscreen extent -3.5,-5.08 3.5,1.27
LQFP-64_10x10x05P [mm]
  oval 0.28x1.8 smd mask+0.051: 1(-3.75,-5.55) 2(-3.25,-5.55) 3(-2.75,-5.55) 4(-2.25,-5.55) 5(-1.75,-5.55) 6(-1.25,-5.55) 7(-0.75,-5.55) 8(-0.25,-5.55) 9(0.25,-5.55) 10(0.75,-5.55) 11(1.25,-5.55) 12(1.75,-5.55) 13(2.25,-5.55) 14(2.75,-5.55) 15(3.25,-5.55) 16(3.75,-5.55) 33(3.75,5.55) 34(3.25,5.55) 35(2.75,5.55) 36(2.25,5.55) 37(1.75,5.55) 38(1.25,5.55) 39(0.75,5.55) 40(0.25,5.55) 41(-0.25,5.55) 42(-0.75,5.55) 43(-1.25,5.55) 44(-1.75,5.55) 45(-2.25,5.55) 46(-2.75,5.55) 47(-3.25,5.55) 48(-3.75,5.55)
  oval 1.8x0.28 smd mask+0.051: 17(5.55,-3.75) 18(5.55,-3.25) 19(5.55,-2.75) 20(5.55,-2.25) 21(5.55,-1.75) 22(5.55,-1.25) 23(5.55,-0.75) 24(5.55,-0.25) 25(5.55,0.25) 26(5.55,0.75) 27(5.55,1.25) 28(5.55,1.75) 29(5.55,2.25) 30(5.55,2.75) 31(5.55,3.25) 32(5.55,3.75) 49(-5.55,3.75) 50(-5.55,3.25) 51(-5.55,2.75) 52(-5.55,2.25) 53(-5.55,1.75) 54(-5.55,1.25) 55(-5.55,0.75) 56(-5.55,0.25) 57(-5.55,-0.25) 58(-5.55,-0.75) 59(-5.55,-1.25) 60(-5.55,-1.75) 61(-5.55,-2.25) 62(-5.55,-2.75) 63(-5.55,-3.25) 64(-5.55,-3.75)
  silkscreen extent -4.55,-6.05 4.25,4.25
MSOP-8 [mil]
  rect 55x16 smd: 1(-98.5,38.5) 2(-98.5,12.5) 3(-98.5,-12.5) 4(-98.5,-38.5) 5(98.5,-38.5) 6(98.5,-12.5) 7(98.5,12.5) 8(98.5,38.5)
  silkscreen extent -60,-60 60,59
R3000F [mm]
  round 2 smd: 1(-3.873,0) 2(3.873,0)
  silkscreen extent -2.6,-1.37 2.6,1.37
SB_0603 [mil] "短接焊点"
  rect 32x40 smd: 1(33.75,0) 2(-33.75,0)
  Top Layer region: 23.75,20 13.75,20 -6.25,0 13.75,-20 23.75,-20
  Top Layer region: -26.25,0 -16.25,0 3.75,20 -26.25,20
  Top Layer region: -26.25,0 -16.25,0 3.75,-20 -26.25,-20
SMA(DO-214AC) [mil]
  rect 50x57.9 smd: 1(-81,0) 2(81,0)
  silkscreen extent -78,-49 79,49
SMA/DO-214AC [mil]
  rect 50x57.9 smd: 1(-66.3,0) 2(66.3,0)
  silkscreen extent -79,-50 79,50
SMD-3215_2P [mil]
  rect 39.37x60 smd: 1(-64.88,0.95) 2(64.87,-0.96)
  silkscreen extent -63,-30 63,29
SMD-5032_2P [mm]
  rect 1.7x2.4 smd: 1(-1.96,0.001) 2(1.96,-0.001)
  silkscreen extent -3.05,-1.52 3.05,1.52
SOD-123 [mil]
  rect 35.8x48 smd: 1(64,0) 2(-64,0)
  silkscreen extent -53,-31 53,31
SOIC-8_150mil [mm]
  oval 0.7x1.8 smd: 1(-1.905,-2.6) 2(-0.635,-2.6) 3(0.635,-2.6) 4(1.905,-2.6) 5(1.905,2.6) 6(0.635,2.6) 7(-0.635,2.6) 8(-1.905,2.6)
  silkscreen extent -2.9,-3.05 2.4,1.4
SOIC-8_208mil [mm]
  oval 2.2x0.7 smd: 1(-3.4,1.905) 2(-3.4,0.635) 3(-3.4,-0.635) 4(-3.4,-1.905) 5(3.4,-1.905) 6(3.4,-0.635) 7(3.4,0.635) 8(3.4,1.905)
  silkscreen extent -3.9,-2.5 1.9,2.95
SOT-23(SOT-23-3) [mm]
  rect 1.25x0.7 smd: 1(1.25,-0.95) 2(1.25,0.95) 3(-1.25,0)
  silkscreen extent -0.65,-1.46 0.9,1.46, body extent -1.5,-1.5 1.5,1.5, height 1.3
SOT-23-5 [mm]
  rect 1.1x0.6 smd: 1(1.4,-0.95) 2(1.4,0) 3(1.4,0.95) 4(-1.4,0.95) 5(-1.4,-0.95)
  silkscreen extent -0.5,-1.87 1.63,1.4
SOT-23-6 [mm]
  rect 1.1x0.6 smd: 1(1.4,-0.95) 2(1.4,0) 3(1.4,0.95) 4(-1.4,0.95) 5(-1.4,0) 6(-1.4,-0.95)
  silkscreen extent -0.5,-1.87 1.72,1.4
SOT-23-8 [mm]
  rect 1.06x0.4 smd: 1(-1.1,0.98) 2(-1.1,0.33) 3(-1.1,-0.33) 4(-1.1,-0.98) 5(1.1,-0.98) 6(1.1,-0.33) 7(1.1,0.33) 8(1.1,0.98)
  silkscreen extent -1.18,-1.61 1.27,1.52
SUPERSOT-6(SSOT-6) [mil]
  rect 24x39.4 smd: 1(-37.4,-51.2) 2(0,-51.2) 3(37.4,-51.2) 4(37.4,51.2) 5(0,51.2) 6(-37.4,51.2)
  silkscreen extent -59,-22 59,22
TEST [mm] "检测"
  round 1.5 hole 1: 1(0,0)
  silkscreen extent -1.02,-1.03 1.01,1.01
TSOP-6 [mil]
  rect 52x22 smd: 1(-47,37) 2(-47,0) 3(-47,-37) 4(47,-37) 5(47,0) 6(47,37)
  silkscreen extent -33,-61 33,61
TSSOP-16 [mil]
  rect 71x16 smd: 1(-118.11,89.5) 2(-118.11,63.5) 3(-118.11,38.5) 4(-118.11,12.5) 5(-118.11,-13.5) 6(-118.11,-38.5) 7(-118.11,-64.5) 8(-118.11,-89.5) 9(118.11,-89.5) 10(118.11,-64.5) 11(118.11,-38.5) 12(118.11,-13.5) 13(118.11,12.5) 14(118.11,38.5) 15(118.11,63.5) 16(118.11,89.5)
  silkscreen extent -122,-107 63,126

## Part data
BT1: "电池底座"
C1 C2 C3 C4 C5 C6 C12 C14 C17 C18 C19 C20 C21 C28 C31 C34 C45 C58 C65 C75 C76: library part 100nF, "贴片电容"
C7 C8 C9 C10 C39 C61 C67: "贴片电容"
C11 C15 C16 C57 C59 C60 C66 C71 C72 C73 C79: library part 10nF, "贴片电容"
C13 C22 C23 C29 C30 C70 C74: library part 1uF, "贴片电容"
C24 C25 C27 C40 C46: library part 10uF, "贴片电容"
C26 C47: library part 33pF, "贴片电容"
C32 C33 C35 C36 C37 C38 C41 C42 C43 C44 C48 C49 C50 C51 C52: library part 4.7nF, "贴片电容(X7R)"
C53 C54 C55 C56: library part 100pF, "贴片电容(X7R)"
C62 C68: library part 47nF, "贴片电容"
C63 C64 C69 C78: library part 1nF, "贴片电容"
C77: library part 1pF, "贴片电容"
D1 D2 D6: "TVS二极管"
D3: "二极管"
D4 D5 D9 D10 D14: "肖特基二极管"
D7: "SPI Flash 华邦电子"
D8: "红绿LED"
D11 D12 D13: "高压二极管"
D15: "ESD二极管"
DSUB1: "DB9串口母头-孔-PCB焊接"
F1: "贴片保险丝"
L1 L3: library part 4.7uH, "功率电感"
L2: library part TRANSCT8, "高压变压器（CCFL）"
L4: library part 1mH, "功率电感"
P1: library part "Header 4"
Q1: "三极管"
R1 R2: library part 7.5K, "贴片电阻"
R3 R13 R15 R36 R41: library part 1K, "贴片电阻"
R4 R7 R9 R12 R14 R25 R37 R39: library part 10K, "贴片电阻"
R5 R6: "贴片电阻"
R8: library part 82K, "贴片电阻"
R10 R26 R27 R28 R29 R31 R32 R33 R34 R35 R38: library part 100K, "贴片电阻"
R11 R20 R23 R30 R43: library part 20K, "贴片电阻"
R16: library part 10M, "贴片电阻"
R17 R18 R19 R22: library part 1M, "贴片电阻"
R21: library part 2K, "贴片电阻"
R24: library part 100M, "贴片电阻"
R40: library part 499, "贴片电阻"
R42: library part 22M, "贴片电阻"
SB1 SB2: library part Res2, "短接焊点"
TEST1: library part SOCKET-STD, "测试点"
U1: "RS232оƬ"
U2 U3 U4 U5: "轨到轨运放"
U6: "单片机"
U8 U10: "LDO电源"
U9 U11: library part JW5017S, "DC-DCоƬ"
U12: "电压比较器"
U13: library part AD5245, "数字电位器"
Y1: library part 32.768KHz, "贴片晶振"
Y2: library part 8MHz, "贴片晶振"

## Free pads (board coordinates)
  round 236.22 hole 125.98: 1(137.8,543.31) 2(137.8,1842.52)

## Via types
v1: diameter 13.78, hole 7.87, Top Layer to Bottom Layer, 224 vias

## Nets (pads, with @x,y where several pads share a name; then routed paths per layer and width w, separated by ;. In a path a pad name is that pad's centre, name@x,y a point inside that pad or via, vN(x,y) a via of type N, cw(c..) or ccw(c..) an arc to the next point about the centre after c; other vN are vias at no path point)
3.3V_VCC1: C3.2 C11.2 C12.1 C14.1 C17.1 C18.1 C23.2 C28.1 C60.2 C71.2 C72.2 C73.2 C79.2 D3.1 D7.3 D7.8 D15.5 R1.2 R9.1 R14.2 R37.1 U2.8 U3.8 U5.8 U6.13 U6.19 U6.32 U6.48 U6.64 U8.2 U12.5 U13.2 | length 6806.1
  Top Layer w6: C72.2 296.18,2019.45 v1(296.5,2019.13) ; U2.8 v1(296.5,2019.13) ; D15.5 342.18,1905 335,1912.18 335,2010.95 326.82,2019.13 v1(296.5,2019.13) ; R37.1 874.68,1949.76 C73.2 ; C73.2@875,1954.76 875,2009.45 U3.8 966.5,2010.95 975,2019.45 975,2179.45 987,2191.45 U13.2 1092.32,2191.45 C79.2@1095,2194.13 ; R1.2@1194.69,1880.32 1195,1880.63 C11.2 v1(1195,2050) ; C71.2 U12.5 1320,1261.62 1330,1271.62 1330,1355 1344.02,1369.02 1394.02,1369.02 1406.77,1381.77 1406.77,1530 ; v1(1405,1560) 1406.77,1558.23 1406.77,1530 ; C14.1 1482.13,1763.64 1502.44,1743.32 U6.13 ; R14.2 1521.76,2152.87 1533.97,2140.66 1533.97,2066.03 1550.31,2049.68 v1(1620,2049.68) 1641.64,2049.68 U6.64 1642.36,2137.7 1644.66,2140 C3.2 ; C60.2 1545,1520.31 1533.31,1532 U5.8 1408.77,1532 1406.77,1530 ; C18.1 v1(1681.73,1560) U6.19 ; C17.1 v1(1937.64,1560) U6.32 ; U6.48 2074.54,1979.54 2090,1995 C12.1 ; v1(2105,1790) 2105,1777.32 2115,1767.32 2132.32,1767.32 2144.69,1779.68 C28.1 ; D7.3 v1(2245,1500) 2245,1465.31 R9.1
  Top Layer w10: v1(2365,1761.17) C23.2 2397.6,1754.09 2397.6,1725 ; v1(2365.88,1725) 2397.6,1725 ; U8.2 2397.6,1725
  Signal Layer2 w6: v1(2245,1500) 2245,1560
  Signal Layer2 w10: v1(296.5,2019.13) 296.5,2092.4 318.54,2114.45 v1(975.31,2114.45) 1027.45,2114.45 1091.9,2050 v1(1195,2050) 2054.69,2050 2065,2039.68 v1(2065,1980) 2065,1805 2080,1790 v1(2105,1790) ; v1(1405,1560) 1502.84,1560 ; v1(1502.84,1745) 1502.84,1560 ; v1@2105,1789.13 2337.04,1789.13 v1(2365,1761.17) ; v1(2365.88,1725) 2365.88,1580.88 2345,1560 2245,1560 v1(1937.64,1560) v1(1681.73,1560) 1502.84,1560
  Bottom Layer w6: D3.1 1613.03,2016.94 1620,2023.91 v1(1620,2049.68)
3.3V_VCC2: C1.1 C30.2 C57.2 D9.1 R4.1 U1.16 U4.8 U7.8 U10.2 | length 3814.4
  Top Layer w6: D9.1@3210.04,697.37 D9.1@3222.93,710.26 ; D9.1 3343.09,696.91 3345,695 ; C57.2 3482,349.58 U4.8
  Top Layer w8: U10.2 2935,1798.92 2948.34,1785.58 2948.34,1750 2968.34,1730 3481.8,1730 3515,1696.8 3515,1130 3505,1120 3370,1120 3345,1095 3345,695 3345,505 3360,490 3498,490 3512,476 3512,369.91 3500.16,358.08 C57.2
  Top Layer w10: U7.8 2235.31,2215 2215,2194.68 2215,2061.25 2247.34,2028.91 2275,2028.91 2295,2008.91 2295,1955 2316.53,1933.47 2465.31,1933.47 ; R4.1 2465.31,1933.47 ; U1.16 2807.84,2036.71 C1.1 2807.84,1933.47 ; U10.2 2820,1798.92 2809.68,1809.24 C30.2 2807.84,1876.84 2807.84,1933.47 ; 2465.31,1933.47 2807.84,1933.47
4.08V_VCC: C20.1 C21.1 C22.2 C24.2 C25.2 C26.2 C29.2 L1.2 R8.2 U8.3 U10.3 | length 1438.5
  Top Layer w6: R8.2 v1(2599.37,1199.69)
  Top Layer w10: C22.2 2463.41,1586.96 ; R8.2 2599.69,1158.77 C26.2 ; C20.1@2633.78,1559.36 C20.1@2634.57,1560.15 ; C29.2 U10.3 ; U10.3@2793.16,1761.05 2793.16,1761.52 2793.63,1761.52 U10.3@2793.16,1761.05
  Top Layer w15: U8.3 2463.41,1586.96 2493.04,1586.96 2520.64,1559.36 C21.1 ; C22.2 C22.2@2465,1524.29
  Top Layer w20: C29.2 2708.16,1698.16 2677.36,1667.36 2597.36,1667.36 2570,1640 C21.1 2570.28,1559.09 v1(2600,1559.09) C24.2 C25.2 2796,1558.09 L1.2
  Signal Layer2 w6: v1(2599.37,1199.69) v1@2599.37,1559.09
AD5245_SCL: U6.58 U13.4 | length 1016.9
  Top Layer w6: U13.4 v1(1044.22,2243.03) ; U6.58 1760.47,2090.8 1768.97,2099.3 1809.85,2099.3 1815,2104.45 v1(1815,2135)
  Signal Layer2 w6: v1(1044.22,2243.03) 1606.97,2243.03 1627.94,2222.06 1627.94,2175 1628,2175 1642.99,2160.01 1809.99,2160.01 1815,2155 v1(1815,2135)
AD5245_SDA: U6.59 U13.5 | length 1048.2
  Top Layer w6: U13.5 v1(959.22,2243.03) ; U6.59 1740.79,2095 1778.18,2132.39 v1(1785,2132.39)
  Signal Layer2 w6: v1(959.22,2243.03) 1016.3,2243.03 1035.2,2224.13 1055,2224.13 1061.9,2231.03 1602,2231.03 1615.94,2217.09 1615.94,2167.07 1635,2148.01 1777.54,2148.01 1785,2140.54 v1(1785,2132.39)
BEAT: R15.1 U6.41 | length 1846.6
  Top Layer w6: U6.41 v1(2090,1841.75) ; R15.1 3485.63,2230.4 v1(3485.63,2180)
  Signal Layer2 w6: v1(2090,1841.75) 2301.43,1841.75 2318,1858.31 2318,2162.97 2335,2179.97 ; 2335,2180 v1(3485.63,2180)
FLASH_CTRL: D7.7 R12.1 U6.37 | length 570.5
  Top Layer w6: U6.37 2055,1763.01 2062.69,1755.32 2181.23,1755.32 2195,1769.09 D7.7 2195,1884.45 2202.96,1892.4 2322.6,1892.4 2340,1875 2340,1840 2350.33,1829.67 R12.1
GND1: BT1.2 C3.1 C7.2 C8.2 C9.2 C10.2 C11.1 C12.2 C13.2 C14.2 C17.2 C22.1 C23.1 C28.2 C31.2 C41.1 C42.1 C43.1 C44.1 C60.1 C63.1 C65.2 C66.2 C67.1 C68.1 C69.2 C70.1 C71.1 C72.1 C73.1 C79.1 D7.4 D15.2 P1.1 pad.1 pad.2 R2.1 R12.2 R31.1 R39.2 SB1.1 SB2.1 U2.4 U3.4 U5.4 U6.12 U6.18 U6.28 U6.31 U6.47 U6.60 U6.63 U8.1 U12.2 U13.3 U13.6 | length 3551.5
  Top Layer w6: D15.2 v1(525,1905) ; U13.6 v1(955,2217.44) U13.3 1050,2217.44 1060.1,2227.55 1060.1,2239.55 1064.03,2243.47 C79.1 C79.1@1091.08,2239.55 ; C11.1 v1(1134.37,1984.15) ; C71.1 v1(1134.69,1305.81) ; C13.2 1194.69,1675.31 v1(1194.69,1710) 1194.69,1739.68 R2.1 ; C7.2 v1(1264.69,2172.13) C8.2 ; C10.2 v1(1295.02,1936.56) 1295.02,1905.94 C9.2 ; U5.4 v1(1345,1455) ; v1(1345,1763.64) C14.2 ; U6.12 v1(1626.11,1763.01) ; C60.1 v1(1617.84,1459.68) ; v1(1585,2145.54) 1585,2180.77 C31.2 ; U6.18 v1(1662.05,1675) ; U6.63 1662.05,1992.1 v1(1674.15,1980) 1715,1980 1721.1,1986.1 U6.60 ; U6.28 v1(1858.9,1673.9) 1911.42,1673.9 1917.95,1667.36 U6.31 ; v1(1937.64,1420.2) C17.2 ; U6.47 v1(2090,1959.86) ; C28.2 v1(2205.31,1962.5) C12.2 ; D7.4 v1(2295,1620) ; v1(2362.39,1522.7) C22.1 ; C23.1 2465.63,1761.49 v1(2465.63,1795.58) R12.2
  Top Layer w10: v1(80.31,2061.95) 80.31,2028.62 89.49,2019.45 C72.1 ; U2.4 v1(535.31,2137.95) ; C69.2 C70.1 v1(710.31,1949.76) R39.2 ; v1(875,1854.76) C73.1 ; U3.4 v1(1114.13,2087.95) ; C63.1 v1(1134.91,1513.03) 1134.91,1545.37 R31.1 ; v1(1352.84,1299.02) U12.2 ; v1(1612.84,1234.02) C66.2 ; C68.1 v1(1742.84,1369.02) ; v1(1872.84,1234.02) C65.2 ; C67.1 v1(2002.84,1369.02) ; C23.1 2472.4,1754.09 v1(2472.4,1726.17) U8.1
  Top Layer w15: v1(2382.5,995) 2341.25,995 v1(2341.25,1025) 2341.25,1055 SB1.1@2382.5,1055
  Top Layer w20: 29.99,2345 29.99,1950.32 pad.2 ; 137.8,47.8 pad.1 ; SB1.1@2382.5,1055 v1(2383.75,1056.25)
  Top Layer w30: v1(63.65,2340) v1@63.65,2342.91
  Signal Layer2 w10: v1(735,1553.82) v1(813.82,1553.82) ; v1(735,1625) v1(811.22,1625)
  Bottom Layer w6: BT1.2@1760,1210 BT1.2
  other v1: 80,50 227.88,50 375.77,50 523.65,50 671.54,50 819.42,50 967.31,50 1115.19,50 1263.08,50 1410.96,50 1558.85,50 1706.73,50 1854.62,50 2002.5,50 2150.38,50 2298.27,50 2446.15,50 2594.04,50 2741.92,50 2889.81,50 3037.69,50 3185.58,50 3333.46,50 3481.35,50 365,269.17 410,269.17 670,269.29 710,269.29 211.54,2340 359.42,2340 507.31,2340 655.19,2340 803.08,2340 950.96,2340 1098.85,2340 1246.73,2340 1394.62,2340 1542.5,2340 1690.38,2340 1838.27,2340 1986.15,2340 2134.04,2340 2281.92,2340 2429.81,2340 2577.69,2340 2725.58,2340 2873.46,2340 3021.35,2340 3169.23,2340 3317.12,2340 3465,2340
GND2: C1.2 C2.1 C6.2 C15.2 C16.1 C20.2 C21.2 C24.1 C25.1 C27.1 C29.1 C30.1 C40.1 C45.2 C46.1 C57.1 C58.2 C59.2 C61.1 C62.1 D1.1 D2.1 D4.1 D6.2 D8.2 D14.1 DSUB1.5 DSUB1.10 DSUB1.11 L4.1 R7.2 R11.1 R23.1 SB1.2 U1.15 U4.4 U7.5 U9.2 U10.1 U11.2 | length 2426.9
  Top Layer w10: U7.5 2325,2065 2338.23,2051.77 2338.23,1995.35 v1(2358.25,1975.33) C15.2 ; C16.1 v1(2404.68,2202.83) R7.2 ; L4.1 v1(2925,804.91) v1(2975,804.91) ; C21.2 C20.2 v1(2670,1498.73) v1(2755,1498.73) 2785.28,1498.73 C25.1 ; v1(2606.52,1761.52) C29.1 ; D1.1 v1(2709.8,2130) D2.1 ; U9.2@2736.85,1199.09 v1(2770,1199.09) ; v1(2741.92,2066.13) U1.15 ; R11.1 v1(2795.31,1124.31) ; C1.2 v1(2902.53,1974.63) ; C30.1 v1(2905.32,1875) ; U10.1 v1(2914.51,1724.12) ; C45.2 2896.54,237.28 2910,223.83 C46.1 v1(2955,172.91) ; D14.1 v1(2935,711.91) v1(2985,711.91) ; v1(2984.09,1285) 2985,1284.09 2985,1269.54 ; v1@2985.91,1255 v1(2985,1255) 2985,1269.54 ; v1(2999.09,983.17) v1(2999.09,1005) C27.1 ; D4.1 2985.46,1269.09 2985,1269.54 ; v1(3105,713.37) 3120,713.37 ; C40.1 3120.04,713.33 3120,713.37 ; v1(3135,713.37) 3120,713.37 ; R23.1 U11.2 U11.2 3170,393.83 v1(3169.96,393.87) ; C6.2 v1(3210,2270.29) ; C2.1@3212.84,2034.63 v1(3247.53,2034.63) ; v1(3285,195.89) U4.4 ; v1(3386.82,849.73) C58.2 ; v1(3388.63,589.73) C59.2 ; D6.2 v1(3470,1225) v1(3470,1250) ; C57.1 v1(3473.5,449.39) ; C62.1 v1(3515,717.91) ; C61.1 v1(3518.18,979.73)
  Top Layer w20: SB1.2 2533.75,1056.25 2545,1045 v1(2545,1020) v1(2597.36,1020) ; D1.1@2708.5,2010.93 D1.1
  other v1: 2710,2095.33
GND3: C48.2 C51.1 C52.1 D13.1 L2.9 SB2.2 | length 6143.3
  Top Layer w15: SB2.2 2450,919.12 2451.25,917.87 v1(2510,917.87)
  Bottom Layer w10: 1105,167.87 1107.66,170.54 C52.1 ; v1(1617.84,917.87) 1617.65,917.68 C48.2 D13.1 1622.37,694.45 L2.9
  Bottom Layer w50: v1(807.84,532.91) v1(807.84,167.87) v1(2842.84,167.87) v1(2842.84,917.87) v1(807.84,917.87) v1(807.84,632.91)
  other v1: 1085,167.87 1370,167.91 1670,167.87 1975,167.87 2270,167.87 2580,167.87 807.84,347.91 2842.84,440 2842.84,765 807.84,777.91 1380,917.87 1910,917.87 2215,917.87 2450.63,918.5 1090,922.91
HIGH_VOLTAGE_TEST: U5.1 U5.2 U6.16 | length 494.7
  Top Layer w6: U5.2 1349,1506 1350,1507 1350,1532 ; U5.1 1350,1532 ; U6.16 1365,1684.27 1350,1669.27 1350,1532
NetBT1_1: BT1.1 D3.2 | length 236.4
  Bottom Layer w6: D3.2 1579.21,1891.9 1592.29,1878.82 BT1.1
NetC2_2: C2.2 U1.2 | length 124.6
  Top Layer w6: U1.2 3091.03,2066.13 3122.53,2034.63 C2.2 C2.2@3152.21,2034.63
NetC4_1: C4.1 U1.1 | length 415.5
  Top Layer w6: U1.1 3040.64,2006.52 3046.58,2000.58 3263.47,2000.58 3272.53,2009.63 3272.53,2089.63 3262.53,2099.63 C4.1@3212.84,2099.63
NetC4_2: C4.2 U1.3 | length 115.1
  Top Layer w6: U1.3 3099.03,2091.13 3107.53,2099.63 C4.2 C4.2@3152.21,2099.63
NetC5_1: C5.1 U1.4 | length 701.4
  Top Layer w6: U1.4 2990.03,2117.13 2983.78,2110.88 2983.78,1999.8 2995,1988.58 3268.44,1988.58 3284.53,2004.66 3284.53,2142.63 3262.53,2164.63 C5.1@3212.84,2164.63
NetC5_2: C5.2 U1.5 | length 120.5
  Top Layer w6: U1.5 3091.03,2143.13 3112.53,2164.63 C5.2 C5.2@3152.21,2164.63
NetC6_1: C6.1 U1.6 | length 160.5
  Top Layer w6: U1.6 3091.03,2168.13 3102.53,2179.63 3102.53,2219.63 3112.53,2229.63 C6.1 C6.1@3152.21,2229.63
NetC7_1: C7.1 U6.4 Y1.2 | length 437.7
  Top Layer w6: C7.1 1325.31,2110 1330.87,2104.45 Y1.2 1463.34,2104.45 1480,2087.78 1480,1945.49 1505,1920.49 U6.4
NetC8_1: C8.1 U6.3 Y1.1 | length 526.6
  Top Layer w6: C8.1 1325.31,2225.64 1333.87,2234.2 Y1.1 1449.94,2234.2 1467.42,2216.71 1467.42,2160 1500,2127.42 1500,1955.17 1515,1940.17 U6.3
NetC9_1: C9.1 U6.6 Y2.1 | length 291.1
  Top Layer w6: C9.1 1391.87,1845 Y2.1 1478.13,1858.13 1501.12,1881.12 U6.6
NetC10_1: C10.1 U6.5 Y2.2 | length 359.7
  Top Layer w6: C10.1 1389.72,2027.81 Y2.2 1405.04,1960.29 1424.2,1941.13 1459.67,1941.13 1500,1900.8 U6.5
NetC13_1: C13.1 R1.1 R2.2 R3.2 U6.8 | length 812
  Top Layer w6: R2.2@1132.21,1745 R2.2@1134.37,1745 ; C13.1 R2.2@1134.37,1745 ; R1.1 v1(1134.37,1840) R2.2@1134.37,1745 ; U6.8 v1(1655,1841.75)
  Signal Layer2 w6: v1(1134.37,1840) 1136.12,1841.75 v1(1655,1841.75)
NetC19_1: C19.1 D4.2 L1.1 U9.6 | length 326.3
  Top Layer w20: C19.1 2830,1319.09 2843.14,1305.94 U9.6 ; 2845,1269.09 D4.2 2906,1321.04 2948.34,1363.38 L1.1
NetC19_2: C19.2 U9.1 | length 83.8
  Top Layer w10: U9.1@2736.85,1236.49 2739.68,1239.33 C19.2
NetC26_1: C26.1 R8.1 R11.2 U9.3 | length 221.4
  Top Layer w10: C26.1 2660.32,1158.77 R8.1 2662.6,1161.69 U9.3@2736.85,1161.69 ; U9.3 2732.91,1090.86 R11.2
NetC27_2: C27.2 D5.2 R10.2 U9.5 | length 730.5
  Top Layer w20: U9.5 2974.09,1199.09 2999.09,1174.09 C27.2 ; R10.2 2998.81,1109.17 C27.2 ; D5.2 3305,1120 3272.91,1087.91 3057.09,1087.91 3036.11,1108.89 C27.2
NetC32_1: C32.1 D11.2 R19.2 | length 206.6
  Bottom Layer w10: R19.2 1375.01,394.21 1376.35,392.87 D11.2 1377.65,300.51 C32.1
NetC32_2: C32.2 C33.1 D12.1 D13.2 | length 311.1
  Bottom Layer w10: C32.2 1497.65,300.51 D12.1 D13.2 1617.65,300.51 C33.1
NetC33_2: C33.2 L2.8 | length 185.9
  Bottom Layer w10: C33.2 1736.31,381.34 1754.14,399.17 L2.8
NetC34_1: C34.1 D9.2 U11.1 | length 439.3
  Top Layer w6: U11.1 v1(3132.6,393.87) 3132.6,400.51 3145,412.91 3225.21,412.91 3240,427.7 3240,507.91 3230,517.91 D9.2
  Top Layer w10: C34.1 3055,358.87 3070.12,343.75 U11.1
NetC34_2: C34.2 D14.2 L3.2 U11.6 | length 348.6
  Top Layer w10: D14.2 2890,557.91 2921.04,526.87 L3.2 2930.04,463.83 2939.68,454.18 C34.2 3132.4,454.18 U11.6
NetC35_1: C35.1 C36.1 C41.2 C42.2 | length 79.3
  Bottom Layer w10: C42.2@387.66,383.66 C42.2 C36.1
NetC35_2: C35.2 C36.2 R16.2 R18.1 | length 189
  Bottom Layer w10: C36.2 R18.1 R16.2
NetC37_1: C37.1 C38.1 C43.2 C44.2 | length 77.7
  Bottom Layer w10: C43.2 C38.1
NetC37_2: C37.2 C38.2 R17.1 R18.2 R24.1 | length 386.3
  Bottom Layer w10: R18.2 C38.2 ; R24.1 C38.2 ; R17.1 C38.2
NetC39_1: C39.1 L2.1 Q1.6 | length 535.4
  Top Layer w10: C39.1@2632,344.17 2632,359.96 2646.17,374.13 Q1.6 2645,401.74 v1(2645,432.91)
  Bottom Layer w10: v1(2645,432.91) 2645,780.07 2657.8,792.87 L2.1
NetC39_2: C39.2 L2.5 Q1.4 | length 369.4
  Top Layer w10: C39.2@2568.81,341.61 2571.37,344.17 Q1.4 ; C39.2 2571.49,299.4 2591.5,279.39 2703.4,279.39 2732.88,308.87 v1(2732.88,397.91)
NetC40_2: C40.2 D10.2 U11.5 | length 965
  Top Layer w10: C40.2 3170,593.33 ; U11.5 3170,593.33 ; D10.2 3377,1148.21 3325,1096.21 3325,770 3300,745 3185.14,745 3170,729.86 3170,593.33
NetC45_1: C45.1 C46.2 C47.2 L2.3 L3.1 R20.1 R21.2 | length 768.5
  Top Layer w10: v1(2755,592.91) 2755,607.6 2760,612.6 R21.2 2800,307.91 2810,297.91 C45.1 C46.2@2955,297.91 ; L3.1@2915,374.37 L3.1@2919.96,369.41 ; L3.1 2955,342.91 C46.2@2955,297.91 ; C47.2 R20.1 3009.65,284.18 2995.91,297.91 C46.2@2955,297.91
NetC47_1: C47.1 R20.2 R23.2 U4.3 | length 252.2
  Top Layer w6: R20.2 R23.2 3220.64,223.55 3237.98,240.89 U4.3
NetC48_1: C48.1 D11.1 D12.2 R22.2 | length 325.7
  Bottom Layer w10: R22.2 1271.35,699.17 D11.1 D12.2 1500.32,701.85 C48.1
NetC49_1: C49.1 C50.1 C51.2 C52.2 | length 77.7
  Bottom Layer w10: C52.2 C50.1
NetC49_2: C49.2 C50.2 R17.2 R19.1 R22.1 | length 322.5
  Bottom Layer w10: R17.2 C50.2 1265.01,580.24 R22.1 1268.98,512.86 R19.1
NetC53_1: C53.1 C54.1 C55.2 C56.2 | length 77.7
  Bottom Layer w10: C54.1 C56.2
NetC53_2: C53.2 C54.2 R16.1 TEST1.1 | length 393.4
  Bottom Layer w10: R16.1 479,1001.91 550,1072.91 C54.2
NetC55_1: C55.1 C56.1 C77.1 D15.1 D15.3 D15.4 D15.6 R42.1 U2.6 | length 1108.8
  Top Layer w6: R42.1 v1(145,2118.44) C77.1 C77.1@146.38,2154.13 ; v1(252.5,2111.95) U2.6 375,2111.95 386,2100.95 D15.4 433,1942 ; D15.6 433,1868 ; D15.1 433,1868 ; D15.3 433,1942 ; v1(490.24,1610.24) 442.76,1610.24 433,1620 433,1868 ; 433,1868 433,1942
  Signal Layer2 w6: v1(145,2118.44) 151.49,2111.95 v1(252.5,2111.95)
  Bottom Layer w6: v1(490.24,1610.24) C56.1
NetC58_1: C58.1 R27.1 R28.2 | length 130
  Top Layer w6: R28.2 R27.1
NetC59_1: C59.1 R29.1 U4.5 | length 496.5
  Top Layer w6: U4.5 3520,214.89 3525,219.89 3525,507.91 3485.32,547.6 C59.1 3485.32,654.41 R29.1
NetC61_2: C61.2 R26.1 R27.2 | length 130
  Top Layer w6: R27.2 R26.1
NetC62_2: C62.2 R28.1 R29.2 | length 130
  Top Layer w6: R29.2 R28.1
NetC63_2: C63.2 R24.2 R31.2 U5.3 | length 1359.4
  Top Layer w6: v1(1195.54,1440.32) C63.2 ; R31.2 1195.85,1481 U5.3 U5.3@1295.34,1478.5
  Signal Layer2 w6: v1(690,815) 690,995 710,1015 1180,1015 1195.54,1030.54 v1(1195.54,1440.32)
  Bottom Layer w6: R24.2 v1(690,815)
NetC64_1: C64.1 R30.1 U4.1 U11.3 | length 309.6
  Top Layer w6: U4.1 3216.66,291.89 3207.4,301.15 U11.3 3207.4,383.66 3216.66,392.91 3247.71,392.91 C64.1 R30.1
NetC64_2: C64.2 R25.1 R30.2 U4.2 | length 332.8
  Top Layer w6: C64.2 R30.2 R25.1 3403.5,279.39 3390,265.89 U4.2
NetC65_1: C65.1 R33.1 R34.2 | length 130
  Top Layer w6: R34.2 R33.1
NetC66_1: C66.1 R35.1 U5.5 | length 298.8
  Top Layer w6: U5.5 1494.84,1420 1503.81,1411.03 1605,1411.03 1612.84,1403.18 C66.1 R35.1
NetC67_2: C67.2 R32.1 R33.2 | length 130
  Top Layer w6: R33.2 R32.1
NetC68_2: C68.2 R34.1 R35.2 | length 130
  Top Layer w6: R35.2 C68.2 R34.1
NetC69_1: C69.1 C70.2 R37.2 R39.1 U2.3 U2.5 U3.5 | length 1058
  Top Layer w6: U2.5 385.31,2137.95 411.31,2111.95 444.13,2111.95 ; v1(444.13,2087.95) 444.13,2111.95 ; U2.3 444.13,2111.95 ; C69.1 v1(647.81,1889.13) C70.2 R37.2 ; v1(835.31,2087.95) U3.5
  Signal Layer2 w6: v1(444.13,2087.95) 647.81,2087.95 ; v1(647.81,1889.13) 647.81,2087.95 ; v1(835.31,2087.95) 647.81,2087.95
NetC74_2: C74.2 U3.1 U3.2 | length 168.7
  Top Layer w6: C74.2 985.31,1999.53 996.73,2010.95 U3.1 U3.2
NetC75_1: C75.1 C78.1 R43.2 U2.1 | length 227.8
  Top Layer w6: U2.1 586.81,2060.95 R43.2 C78.1 C75.1@720,2064.13
NetC75_2: C75.2 R40.1 | length 64.8
  Top Layer w6: C75.2 720.63,2124.76 R40.1
NetC76_1: C76.1 C77.2 R42.2 U2.7 | length 226.8
  Top Layer w6: C76.1 204.26,2218.39 204.26,2085.5 205.7,2086.95 U2.7
NetC76_2: C76.2 R41.1 | length 64.2
  Top Layer w6: C76.2 329.37,2219.13 R41.1
NetC78_2: C78.2 R41.2 R43.1 U2.2 | length 462.7
  Top Layer w6: R41.2 560,2219.45 590,2189.45 R43.1 ; U2.2 532.5,2086.95 545,2099.45 545,2114.45 555.31,2124.76 R43.1 ; C78.2 R43.1
NetD8_1: D8.1 R15.2 | length 85.3
  Top Layer w6: D8.1 3376.07,2222.05 3384.74,2230.72 R15.2
NetD8_3: D8.3 R13.2 | length 83.7
  Top Layer w6: D8.3 3419.71,2022.05 R13.2
NetL2_2: L2.2 Q1.3 R21.1 | length 491.5
  Top Layer w10: Q1.3 2571.37,469.07 2582.53,457.91 2720,457.91 2732.84,470.76 2732.84,667.91 2738.16,673.23 2755,673.23 ; v1(2755,692.91) 2755,673.23 ; R21.1 2755,673.23
NetL2_4: L2.4 Q1.1 | length 61.1
  Top Layer w10: Q1.1 2651.55,497.6 v1(2705,497.6)
NetL4_2: L4.2 Q1.2 Q1.5 | length 347.3
  Top Layer w10: L4.2 2538.16,570.48 2538.16,457.91 2555.63,440.44 2600,440.44 2608.77,431.67 Q1.5 ; Q1.2 L4.2@2608.77,600.51
NetR4_2: R4.2 R5.1 U7.6 | length 445.3
  Top Layer w6: U7.6 2338.23,2115 2365,2088.23 v1(2365,2057.29) 2381.96,2040.33 R5.1 R5.1@2399.69,2045.33 ; v1(2362.39,1895) R4.2
  Signal Layer2 w6: v1(2362.39,1895) 2395,1895 2404.68,1904.68 2404.68,2050.32 2397.71,2057.29 v1(2365,2057.29)
NetR6_1: R6.1 R7.1 U7.7 | length 415.4
  Top Layer w6: U7.7 2361.51,2165 ; R6.1@2394.69,2095.33 R6.1 2371.18,2105.33 2361.51,2115 2361.51,2165 ; R7.1 2465.31,2265.01 2460,2270.33 2371.84,2270.33 2361.51,2260 2361.51,2165
NetR10_1: R10.1 U9.4 | length 186.3
  Top Layer w10: U9.4 2843.14,1061.85 2856.46,1048.54 R10.1
NetR25_2: R25.2 U4.6 U4.7 | length 253.1
  Top Layer w6: R25.2 3428.5,418.71 3438.5,408.71 3438.5,323.39 3433.5,318.39 3433.5,273.39 3441,265.89 U4.7 U4.6
NetR36_1: R36.1 R38.2 U12.3 | length 187.9
  Top Layer w6: U12.3 1450.76,1336.42 R38.2 1472.53,1329.33 1533.16,1268.7 R36.1
NetR36_2: R36.2 U5.6 U5.7 | length 373.4
  Top Layer w6: U5.6 1443.84,1481 1441.34,1483.5 ; U5.7 1448.84,1506 1441.34,1498.5 1441.34,1483.5 ; R36.2 1547.84,1377.16 1533.97,1391.03 1450.31,1391.03 1441.34,1400 1441.34,1483.5
NetR40_2: R40.2 U3.6 U13.7 | length 329
  Top Layer w6: R40.2 787.18,2061.95 U3.6 913.13,2061.95 920.31,2069.13 920.31,2119.13 910.31,2129.13 895.31,2129.13 880.31,2144.13 880.31,2184.13 887.64,2191.45 U13.7
NetU3_3: U3.3 U3.7 U13.1 | length 311.3
  Top Layer w6: U3.7 v1(923.13,2036.95) ; U13.1 v1(1013.3,2061.95) U3.3
  Signal Layer2 w6: v1(923.13,2036.95) 960.31,2036.95 985.31,2061.95 v1(1013.3,2061.95)
NRST: C31.1 P1.4 R14.1 U6.7 | length 765.3
  Top Layer w6: U6.7 1633.79,1861.43 1650,1877.64 1650,1972.94 1613.49,2009.45 1527.55,2009.45 1512,2025 1512,2132.39 1489.39,2155 1489.39,2232.86 1500,2243.47 R14.1 C31.1 1622.25,2243.47 1641.59,2224.13 P1.4
PWM1: R26.2 U6.26 | length 2224.5
  Top Layer w6: U6.26 1820,1612.93 v1(1820,1515) ; R26.2 v1(3485.63,1087.91)
  Signal Layer2 w6: v1(1820,1515) 1820,1105 1837.09,1087.91 v1(3485.63,1087.91)
PWM2: R32.2 U6.29 | length 459.1
  Top Layer w6: v1(1878.58,1538.03) U6.29 ; R32.2 v1(2067.84,1369.02)
  Signal Layer2 w6: v1(1878.58,1538.03) 1878.58,1406.42 1895,1390 2060,1390 2067.84,1382.16 v1(2067.84,1369.02)
RS232_RX: DSUB1.2 U1.13 | length 1135.7
  Top Layer w6: U1.13 v1(2877.22,2117.13)
  Signal Layer2 w6: v1(2877.22,2117.13) 2877.22,2080 2887.22,2070 3015,2070 3028,2057 3028,1282 3040.7,1269.3 DSUB1.2
RS232_TX: DSUB1.3 U1.14 | length 1006
  Top Layer w6: U1.14 v1(2915,2091.13)
  Signal Layer2 w6: v1(2915,2091.13) 3023.5,2091.13 3040,2074.63 3040,1388.66 3050.7,1377.96 DSUB1.3
RS458_USART3_CTRL: U6.53 U7.2 U7.3 | length 490.7
  Top Layer w6: U6.53 v1(1858.9,2098.9) ; v1(2035,2165) U7.2 2134.63,2165 2145,2154.63 2145,2123.23 2136.77,2115 U7.3
  Signal Layer2 w6: v1(1858.9,2098.9) 1858.9,2153.9 1870,2165 v1(2035,2165)
RS-485A: C15.1 D1.2 DSUB1.6 R5.2 | length 1622
  Top Layer w6: C15.1 R5.2 2506.46,2040.33 2537.16,2009.63 D1.2 2624.63,2009.63 v1(2625,2010)
  Signal Layer2 w6: v1(2625,2010) 2985,2010 3004,1991 3004,1221 3015,1210 3220.03,1210 DSUB1.6
RS-485B: C16.2 D2.2 DSUB1.7 R6.2 | length 1862
  Top Layer w6: R6.2 C16.2 2525.7,2170.33 2550,2194.63 D2.2 2643.21,2194.63 2655,2182.84 v1(2655,2045)
  Signal Layer2 w6: v1(2655,2045) 2985,2045 3016,2014 3016,1235.97 3029.97,1222 3156.55,1222 3168.57,1234.02 3168.57,1312.2 3180,1323.63 DSUB1.7
RUNING: R13.1 U6.40 | length 1922.6
  Top Layer w6: U6.40 v1(2105,1822.06) ; R13.1 3485.63,2027.33 v1(3485.63,2080)
  Signal Layer2 w6: v1(2105,1822.06) 2317.06,1822.06 2330,1835 2330,2158 2340,2168 3257,2168 3285,2140 3285,2100 3305,2080 v1(3485.63,2080)
SDI-12: DSUB1.1
SHDN: U6.25 U11.4 | length 2746.2
  Top Layer w6: v1(1799.84,1538.03) U6.25 ; U11.4 v1(3207.4,490.77)
  Signal Layer2 w6: v1(1799.84,1538.03) 1799.84,1085.16 1810,1075 3290,1075 3310,1055 3310,505 3295.77,490.77 v1(3207.4,490.77)
SIGNAL_DOWN: R38.1 U6.17 U12.1 | length 594.5
  Top Layer w6: U12.1@1387.96,1259.02 1448.16,1259.02 R38.1 1458.16,1269.02 v1(1502.84,1269.02) ; v1(1642.36,1540) U6.17
  Signal Layer2 w6: v1(1502.84,1269.02) 1627.94,1269.02 1642.36,1283.44 v1(1642.36,1540)
SIGNAL_OUT: C74.1 R3.1 U6.9 U12.4 | length 1342.1
  Top Layer w6: v1(985.31,1850.31) C74.1 ; R3.1 v1(1237.16,1805) ; v1(1237.16,1336.03) 1277.33,1336.03 U12.4 ; U6.9 v1(1627.94,1822.06)
  Signal Layer2 w6: v1(985.31,1850.31) 985.31,1814.09 994.4,1805 v1(1237.16,1805) ; v1(1237.16,1336.03) v1(1237.16,1805) ; v1(1627.94,1822.06) 1627.94,1812.94 1620,1805 v1(1237.16,1805)
SPI1_MISO: D7.2 U6.35 | length 338.4
  Top Layer w6: U6.35 2175,1723.64 2195,1703.64 D7.2
SPI1_MOSI: D7.5 U6.36 | length 361.1
  Top Layer w6: U6.36 2278.32,1743.32 2295,1760 D7.5
SPI1_NSS: D7.1 R9.2 U6.33 | length 378.3
  Top Layer w6: U6.33 2125.73,1684.27 2145,1665 D7.1 2145,1475 2155,1465 R9.2
SPI1_SCK: D7.6 U6.34 | length 354.4
  Top Layer w6: U6.34 v1(2065,1703.95) ; v1(2245,1761.52) D7.6
  Signal Layer2 w6: v1(2065,1703.95) 2235,1703.95 2245,1713.95 v1(2245,1761.52)
SWCLK: P1.3 U6.49 | length 304.3
  Top Layer w6: P1.3 1785,2175 1800,2160 1880,2160 1890,2150 1925,2150 1937.64,2137.36 U6.49
SWDIO: P1.2 U6.46 | length 436.1
  Top Layer w6: P1.2 1885,2177.03 1897.4,2164.63 1960.37,2164.63 1970,2155 1970,2010 1937.64,1977.64 1937.64,1947.36 1944.83,1940.17 U6.46
USART1_RX: U1.12 U6.43 | length 1421.1
  Top Layer w6: U6.43 v1(2090,1881.12) ; U1.12 2894.32,2143.13 2906,2154.82 2906,2234 v1(2895,2245)
  Signal Layer2 w6: v1(2090,1881.12) 2156.12,1881.12 2173,1898 2173,2209.97 2208.03,2245 v1(2895,2245)
USART1_TX: U1.11 U6.42 | length 1341.1
  Top Layer w6: U6.42 v1(2105,1861.43) ; U1.11 2868.13,2168.13 2877.22,2177.22 v1(2877.22,2222.78)
  Signal Layer2 w6: v1(2105,1861.43) 2169.43,1861.43 2185,1877 2185,2205 2213,2233 2867,2233 v1(2877.22,2222.78)
USART3_RX: U6.52 U7.1 | length 468.4
  Top Layer w6: U6.52 v1(1878.58,2122.92) ; U7.1 v1(2140,2215)
  Signal Layer2 w6: v1(1878.58,2122.92) 2122.92,2122.92 2140,2140 v1(2140,2215)
USART3_TX: U6.51 U7.4 | length 268.1
  Top Layer w6: U6.51 v1(1898.27,2098.27) ; v1(2015,2098.27) 2015,2080 2030,2065 U7.4
  Signal Layer2 w6: v1(1898.27,2098.27) v1(2015,2098.27) v1@2021.36,2098.27
VBAT-3V: D3.3 U6.1 | length 90.7
  Top Layer w6: v1(1520.46,1979.54) U6.1
  Bottom Layer w6: D3.3 v1(1520.46,1979.54)
VCC_6V~20V: D5.1 D6.1 D10.1 F1.2 | length 278.5
  Top Layer w20: D5.1 3305.7,1344.7 D10.1@3377,1344.7 ; D10.1 D10.1@3377,1344.7 ; F1.2 3377,1453 D10.1@3377,1344.7 ; D6.1 D10.1@3377,1344.7
VIN_7V~20V: DSUB1.9 F1.1 | length 228.5
  Top Layer w20: DSUB1.9 3225,1602 3255,1632 F1.1
pads on no net: BT1.0 C18.2 DSUB1.4 DSUB1.8 L2.6 L2.7 L2.10 U1.7 U1.8 U1.9 U1.10 U6.2 U6.10 U6.11 U6.14 U6.15 U6.20 U6.21 U6.22 U6.23 U6.24 U6.27 U6.30 U6.38 U6.39 U6.44 U6.45 U6.50 U6.54 U6.55 U6.56 U6.57 U6.61 U6.62 U13.8

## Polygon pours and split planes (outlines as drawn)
GND1 on Bottom Layer "Signal Layer 2-No Net" (solid, pour order 18): 10,2285 2235,2285 2235,1920 2504.95,1920 2505.03,955 780,955 780,1680 300,1680 300,2010 10,2010
GND2 on Bottom Layer "Signal Layer 2-No Net" (solid, pour order 4): 2245,2285 2245,1930 2515,1930 2515,955 2880,955 2880,100 3535,100 3535,2285
GND1 on Signal Layer1 "Signal Layer 2-No Net" (solid, pour order 16): 10,2000 290,2000 290,1681.99 290,1670.08 769.92,1670.08 770,1670 770,100 10,100 10,940 398.82,940 400,940 400,1445 10,1445
GND1 on Signal Layer1 "Signal Layer 2-No Net" (solid, pour order 10): 10,2285 2235,2285 2235,1920 2505,1920 2505,955 780,955 780,1680 300,1680 300,1980 300,2000 300,2010 10,2010
GND2 on Signal Layer1 "Signal Layer 2-No Net" (solid, pour order 12): 2245,2285 3535,2285 3535,100 2880,100 2880,955 2515,955 2515,1929.89 2245,1930.08
GND3 on Signal Layer1 "Signal Layer 2-No Net" (solid, pour order 0): 780,945 2870,945 2870,100 780,100

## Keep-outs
Keep-Out Layer:
  lines w10: 393.7,947.01 393.7,1439.13 0,1439.13 0,2385.83 3543.31,2385.83 3543.31,0 0,0 0,947.01 393.73,947.01

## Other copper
Top Layer:
  region net GND1: 3530,2375 15,2375 15,2295 3530,2295
  rectangle net GND1: 15,10 3530,90
  text "DATE:20190722" at 1062.84,592.91 h98.43
  text "www.hnzygd.cn" at 1062.84,522.91 h98.43
  text "中子法测量土壤水分_V1.5" at 1062.84,407.91 h86.61
  text "COPYRIGHT  <C> 2018 ZYGD LTD" at 1062.84,337.91 h90.55
Signal Layer1:
  pour cut-out: 550,1127.91 cw(c550,1192.91) 485,1192.91 cw(c550,1192.91) 550,1257.91 cw(c550,1192.91) 615,1192.91 cw(c550,1192.91)
  pour cut-out: 550,1127.91 cw(c550,1192.91) 485,1192.91 cw(c550,1192.91) 550,1257.91 cw(c550,1192.91) 615,1192.91 cw(c550,1192.91)
Bottom Layer:
  region net GND1: 3530,2375 15,2375 15,2295 3530,2295
  rectangle net GND1: 15,10 3530,90
  rectangle net NetC53_2: 440,1142.76 660,1242.76
  pour cut-out: 550,1192.91 505,1147.91 505,1147.76

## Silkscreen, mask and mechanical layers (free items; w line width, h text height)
Top Overlay:
  lines w6: 0,1566.93 275.59,1566.93 275.59,1960.63 0,1960.63 ; 0.98,818.9 275.59,818.9 275.59,425.2 2.28,425.2
Top Solder:
  region: 3530,2375 15,2375 15,2295 3530,2295
  rectangle: 15,10 3530,90
Bottom Solder:
  rectangle: 440,1142.76 660,1242.76
  region: 3530,2375 15,2375 15,2295 3530,2295
  rectangle: 15,10 3530,90
  lines w50: 807.84,532.87 807.84,167.87 2842.84,167.87 2842.84,917.87 807.84,917.87 807.84,632.87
